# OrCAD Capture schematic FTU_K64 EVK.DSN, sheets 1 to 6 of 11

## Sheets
1 PAGE01 Diagram&Revision History: title: K64 FTU EVK; rev: X; company: Freescale Semiconductor; note: SCH-XXXXX PDF: SPF-XXXXX; note: 6501 William Cannon Drive West; note: Austin, TX 78735-8598
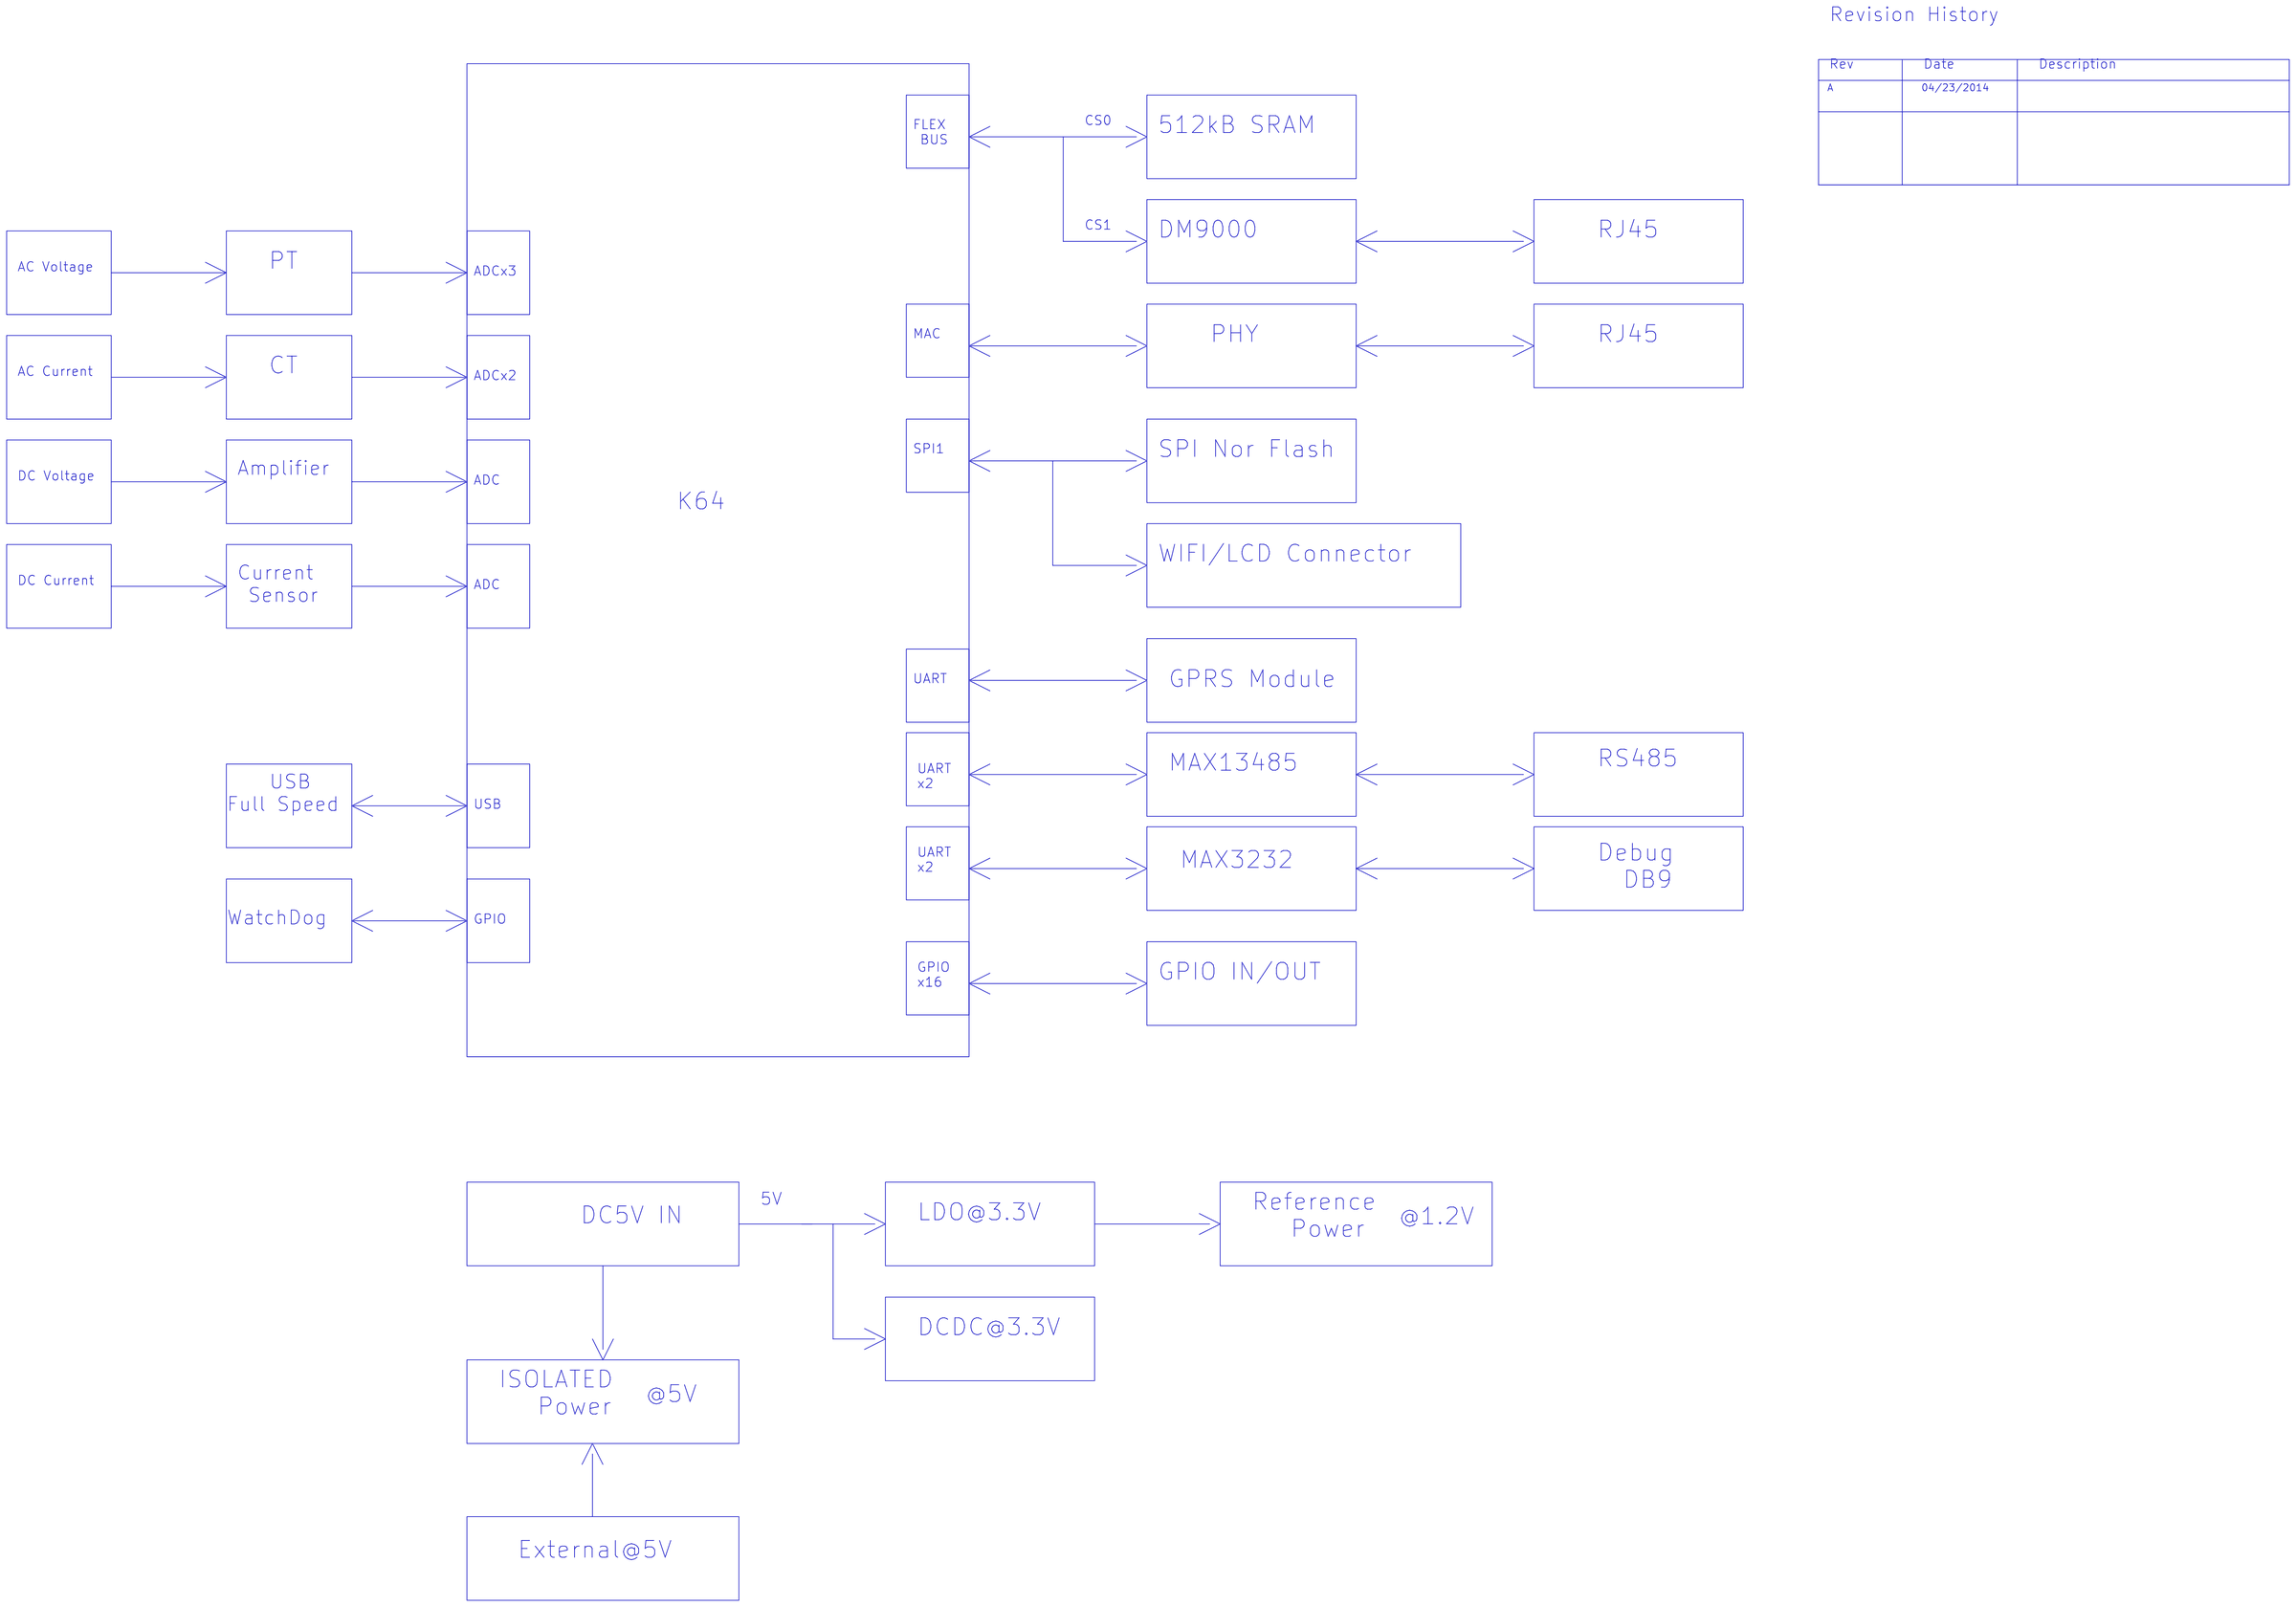
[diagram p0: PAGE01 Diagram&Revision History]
2 PAGE02 MCU: size A2
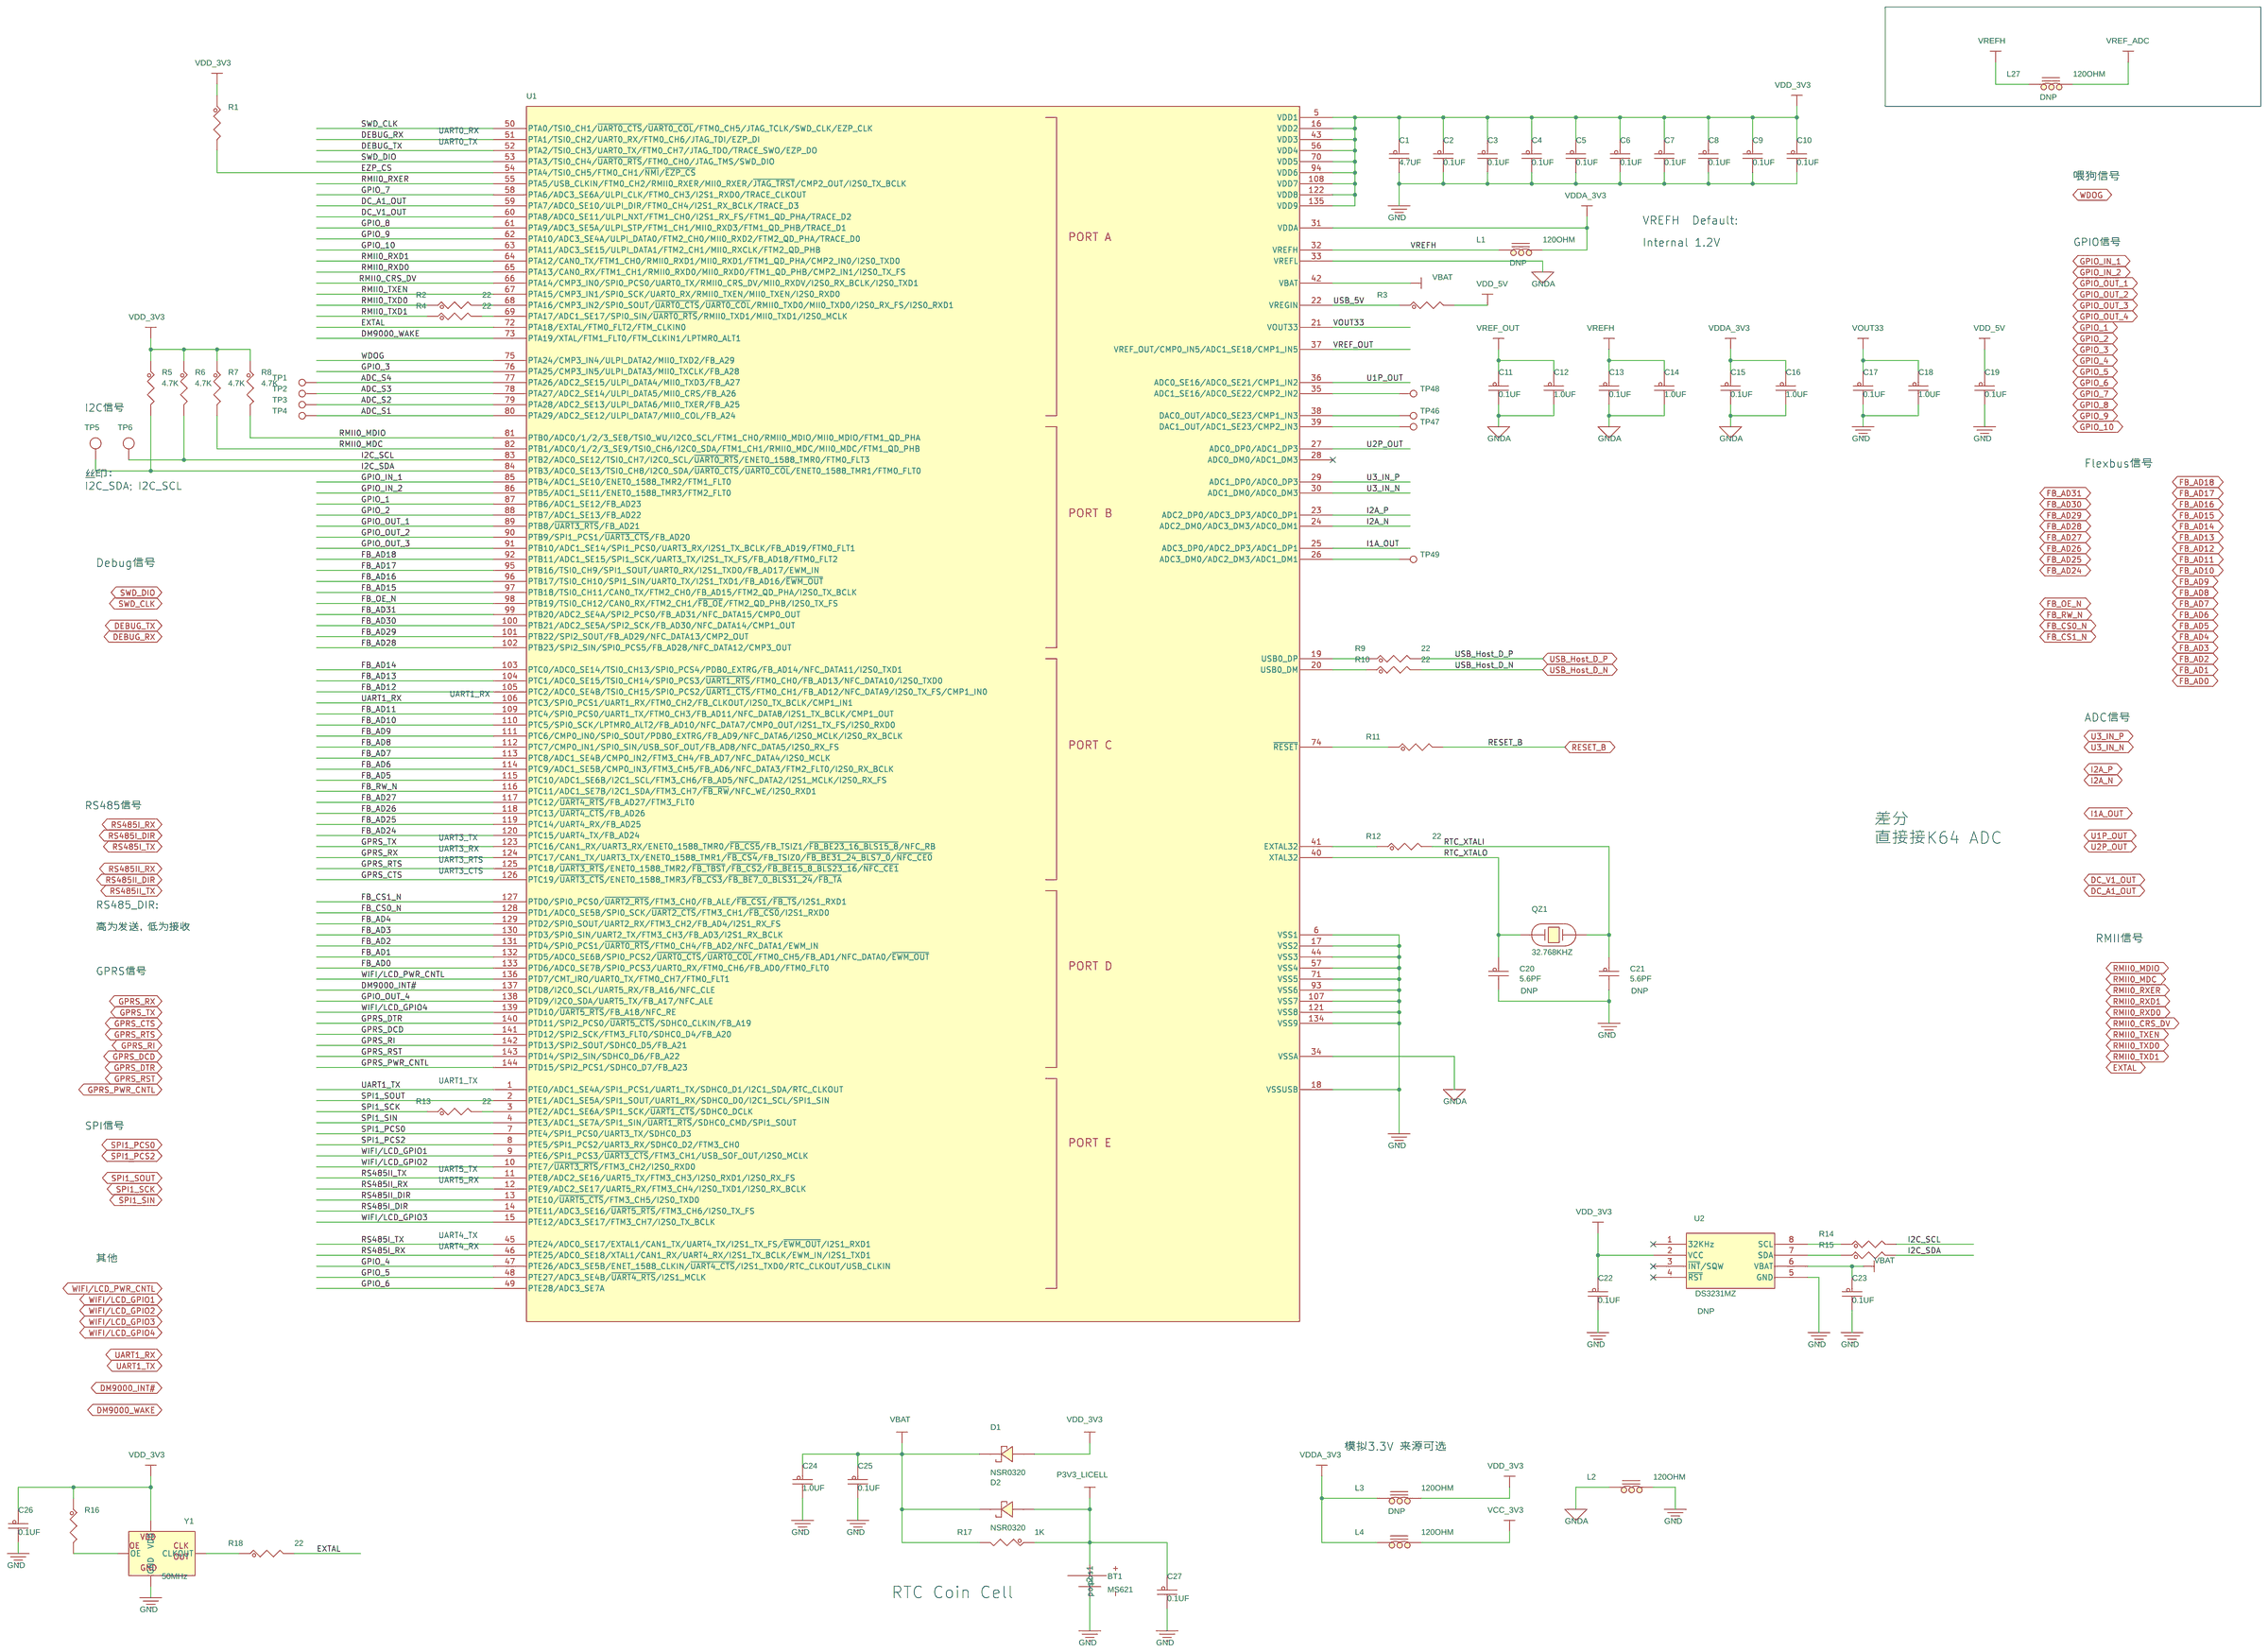
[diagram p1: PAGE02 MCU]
3 PAGE03 Memory: size A4
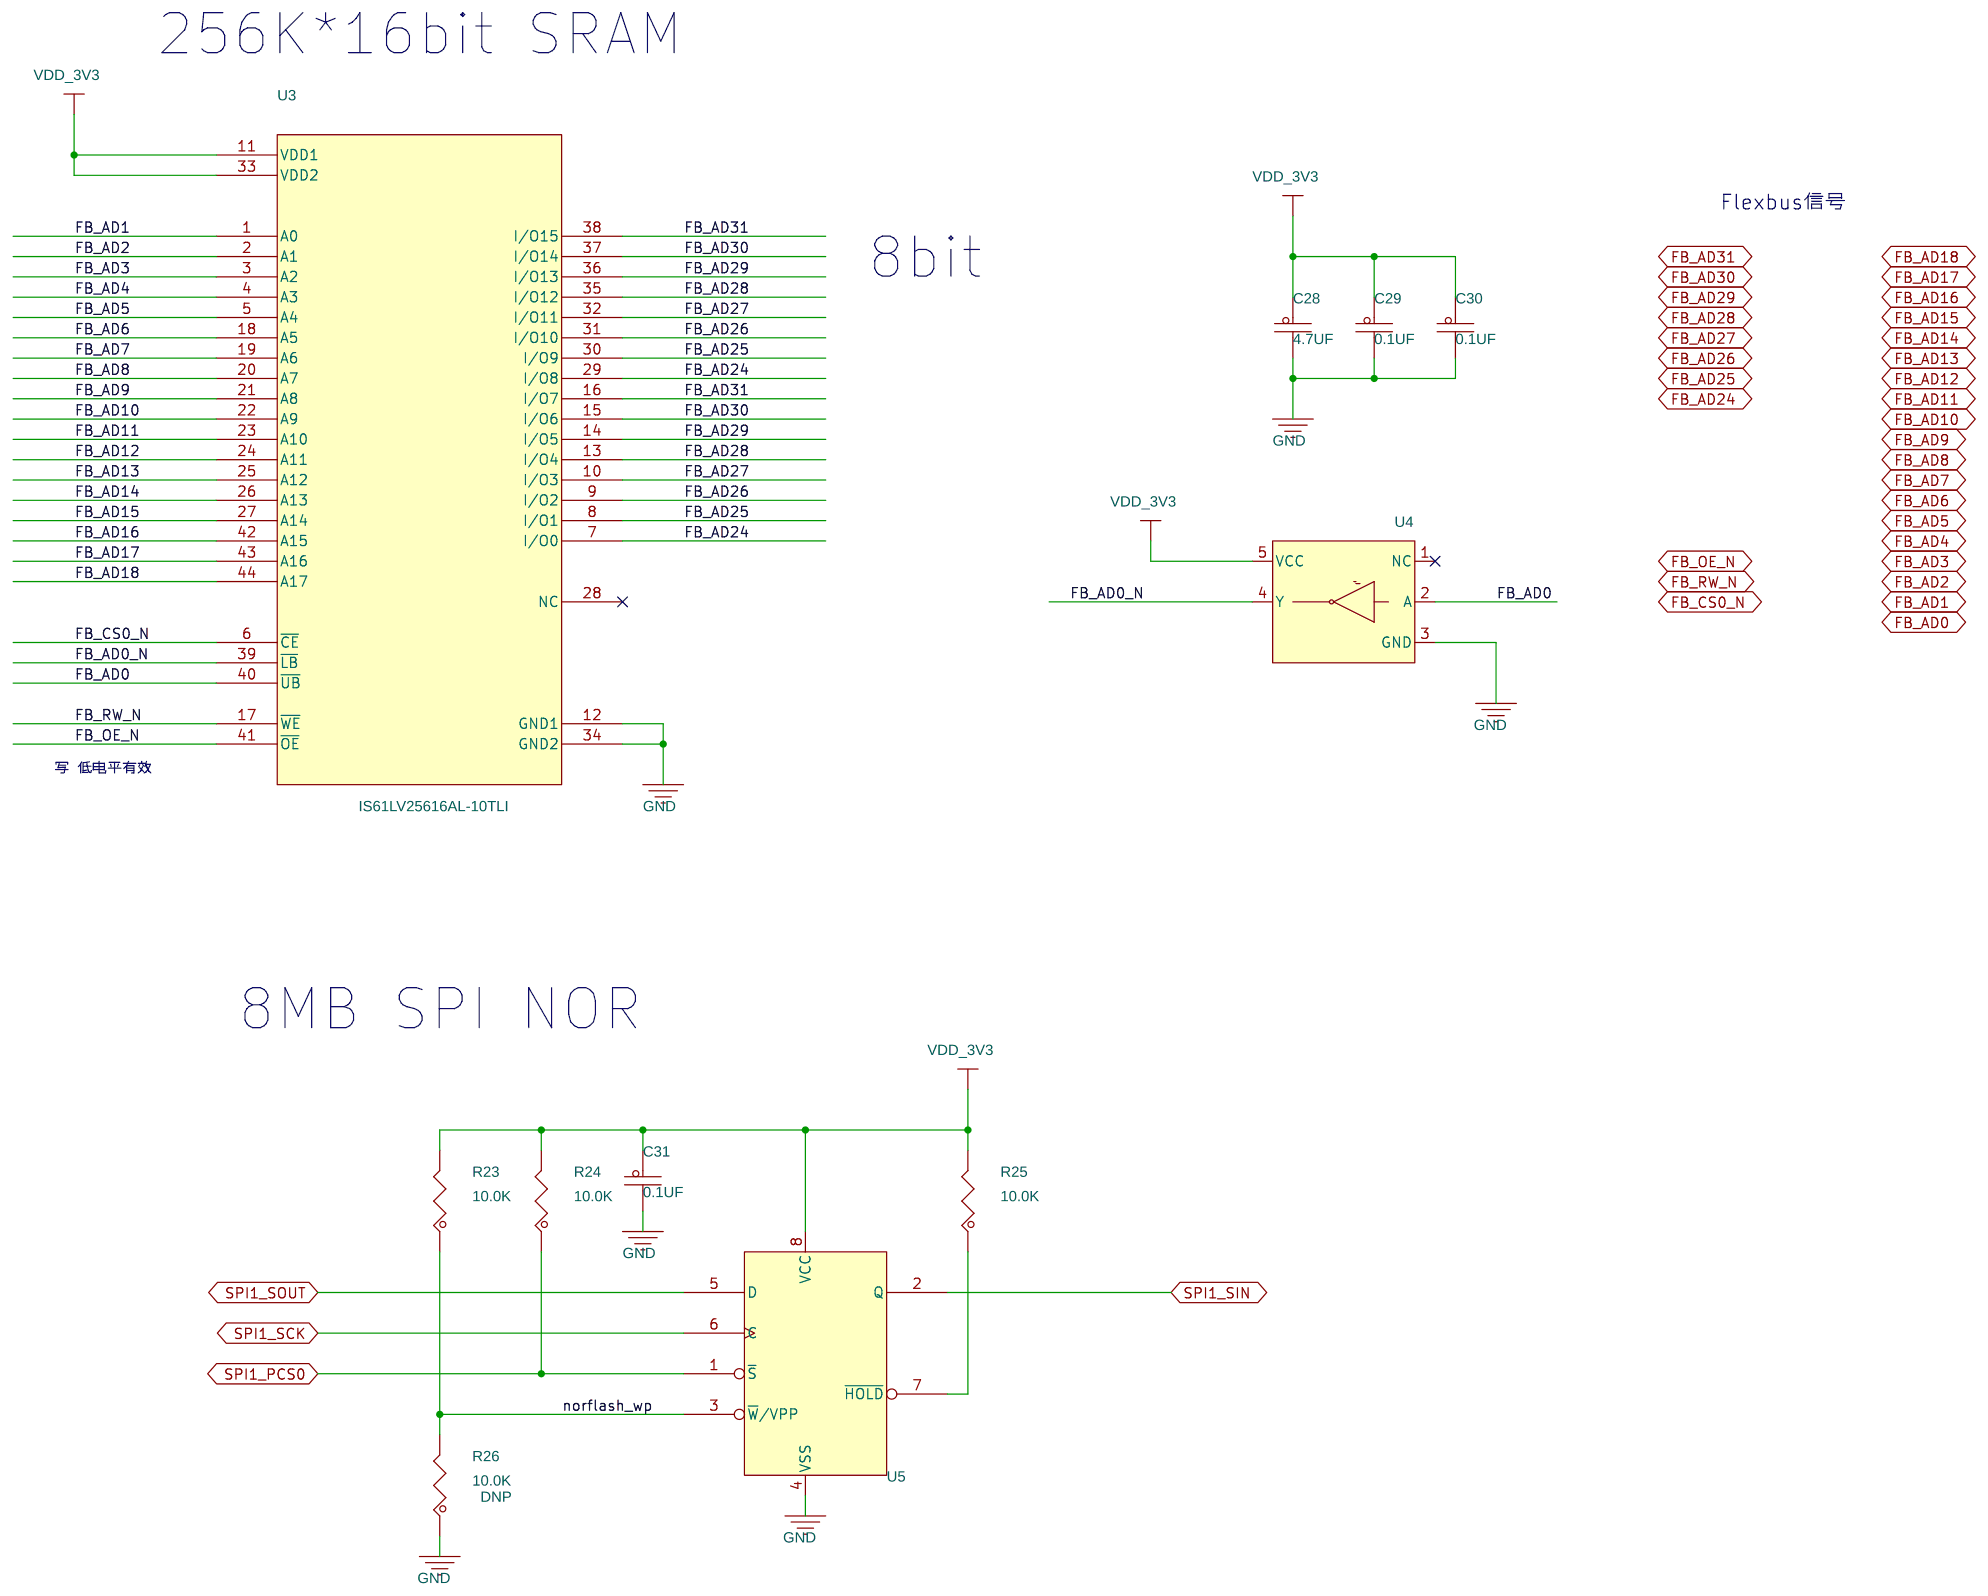
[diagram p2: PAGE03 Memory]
4 PAGE04 ADC: size C
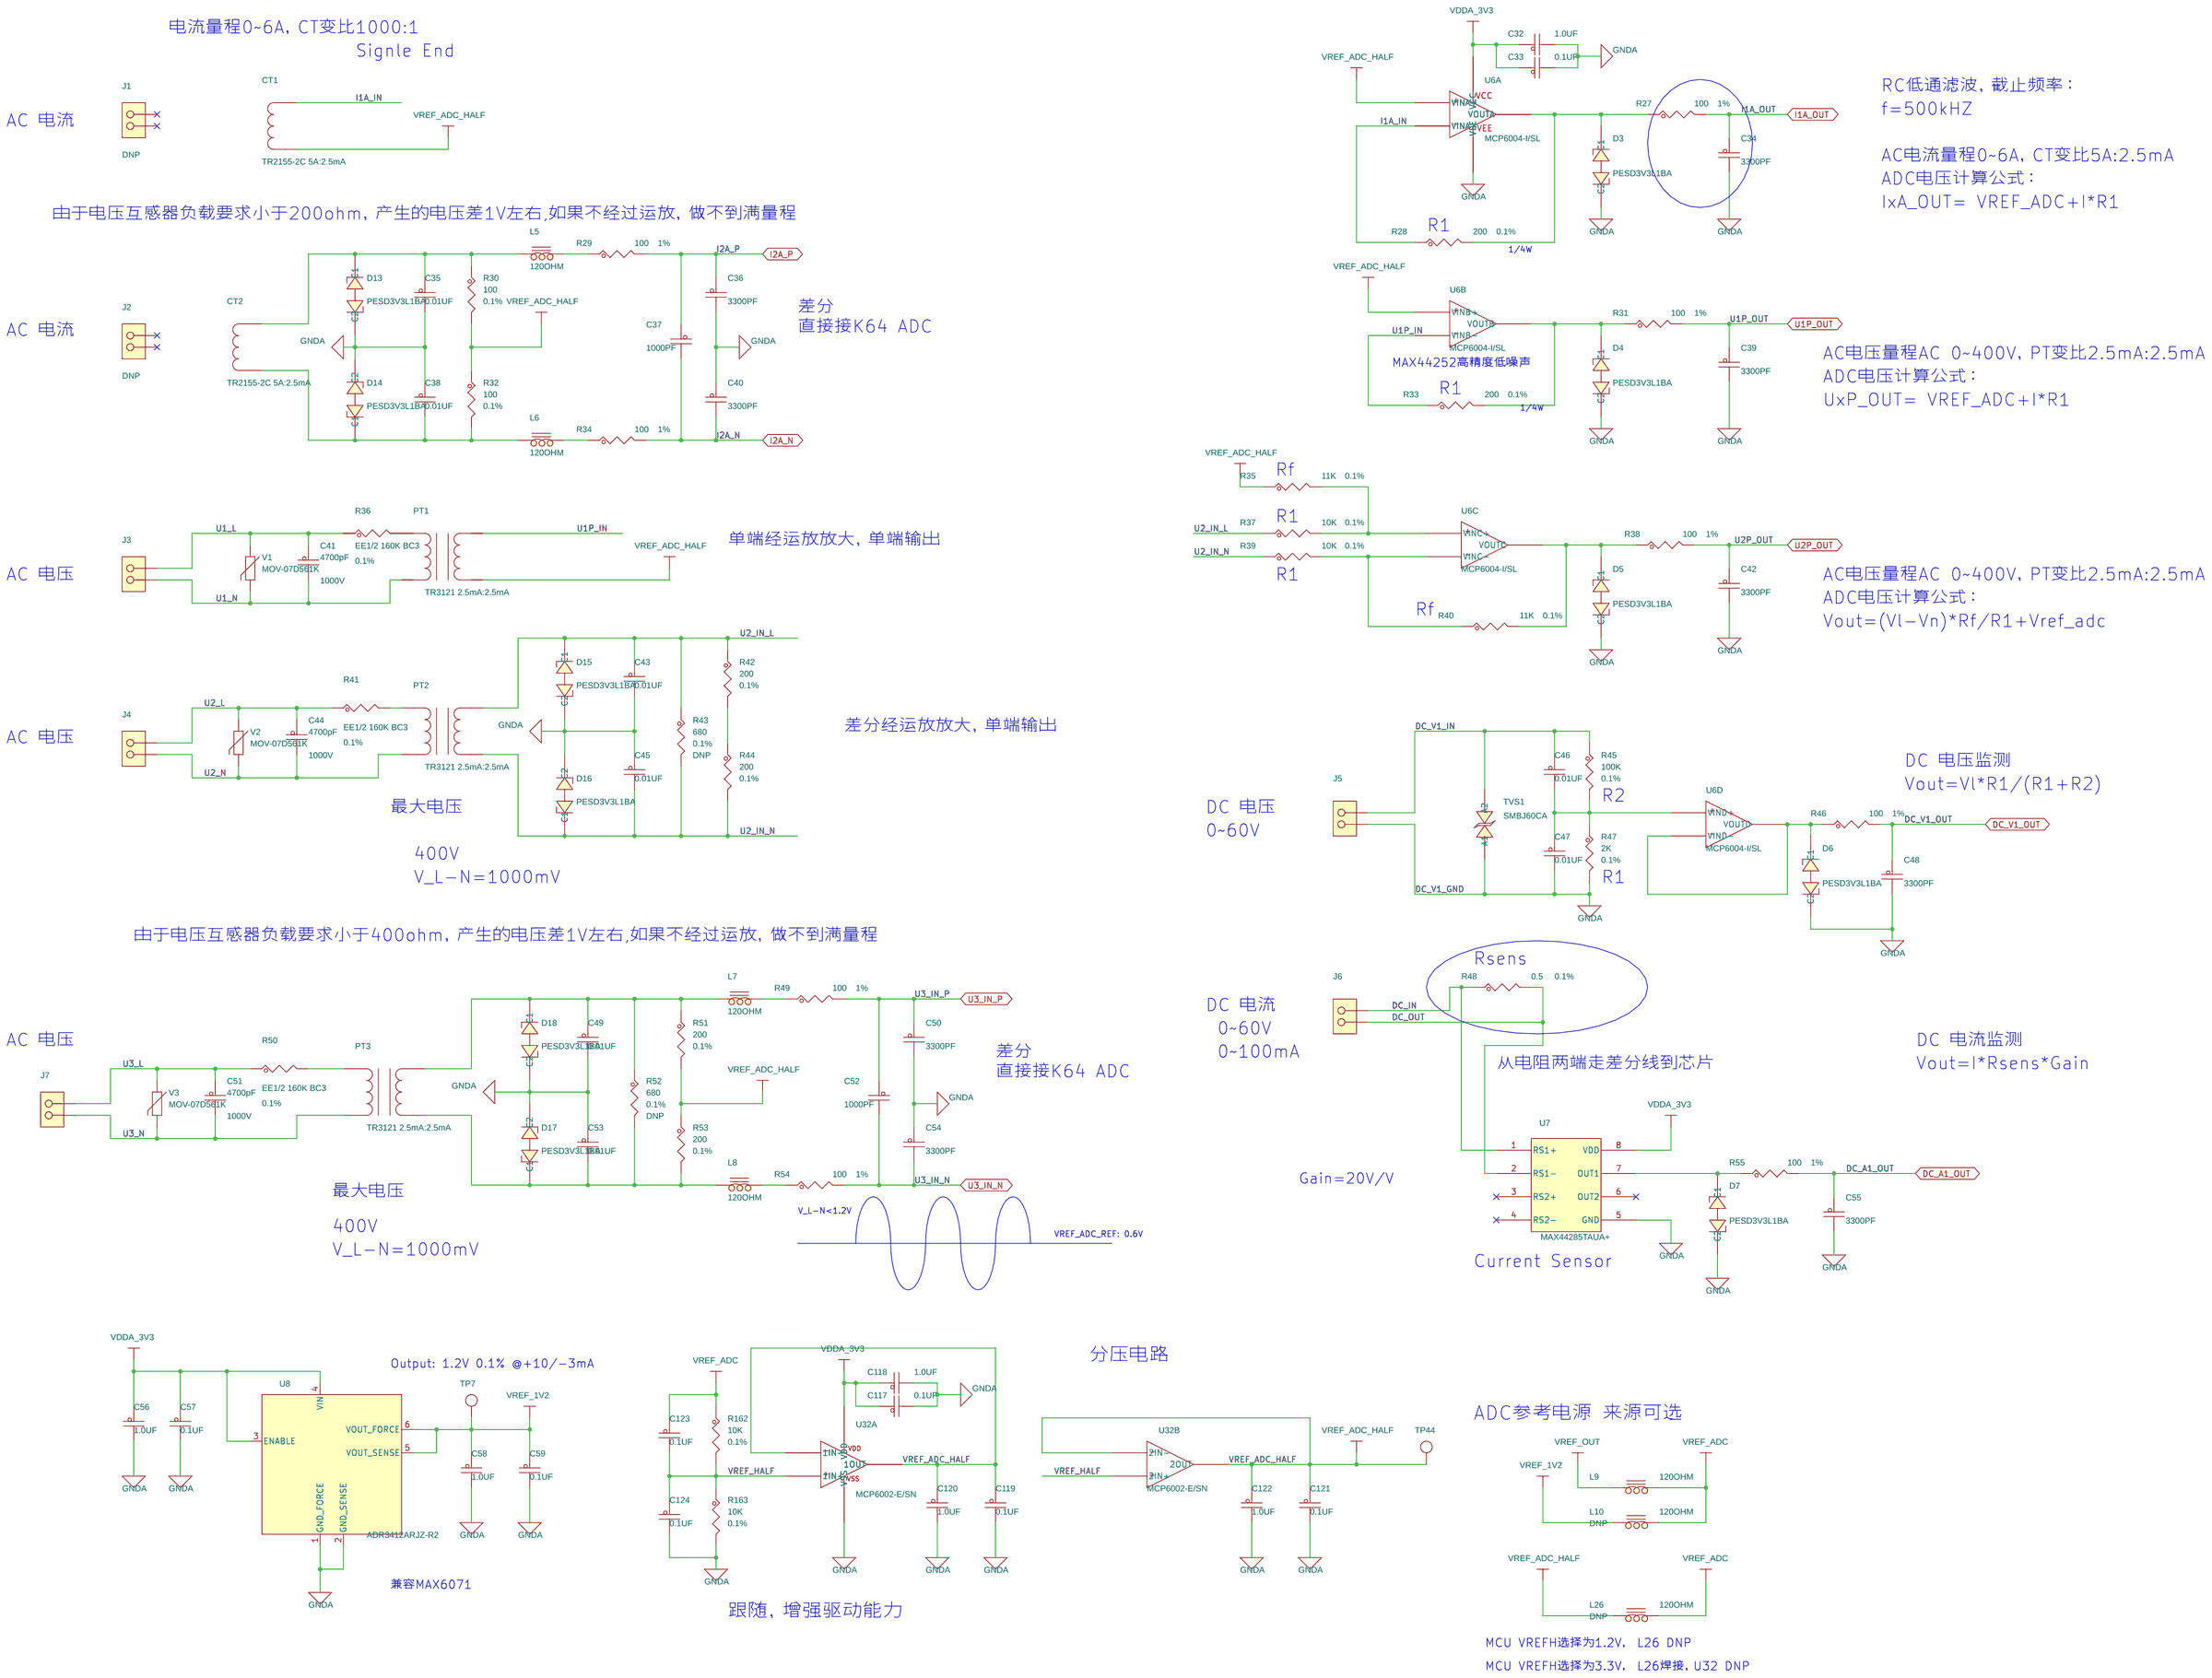
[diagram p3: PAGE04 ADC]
5 PAGE05 Ethernet: size A2
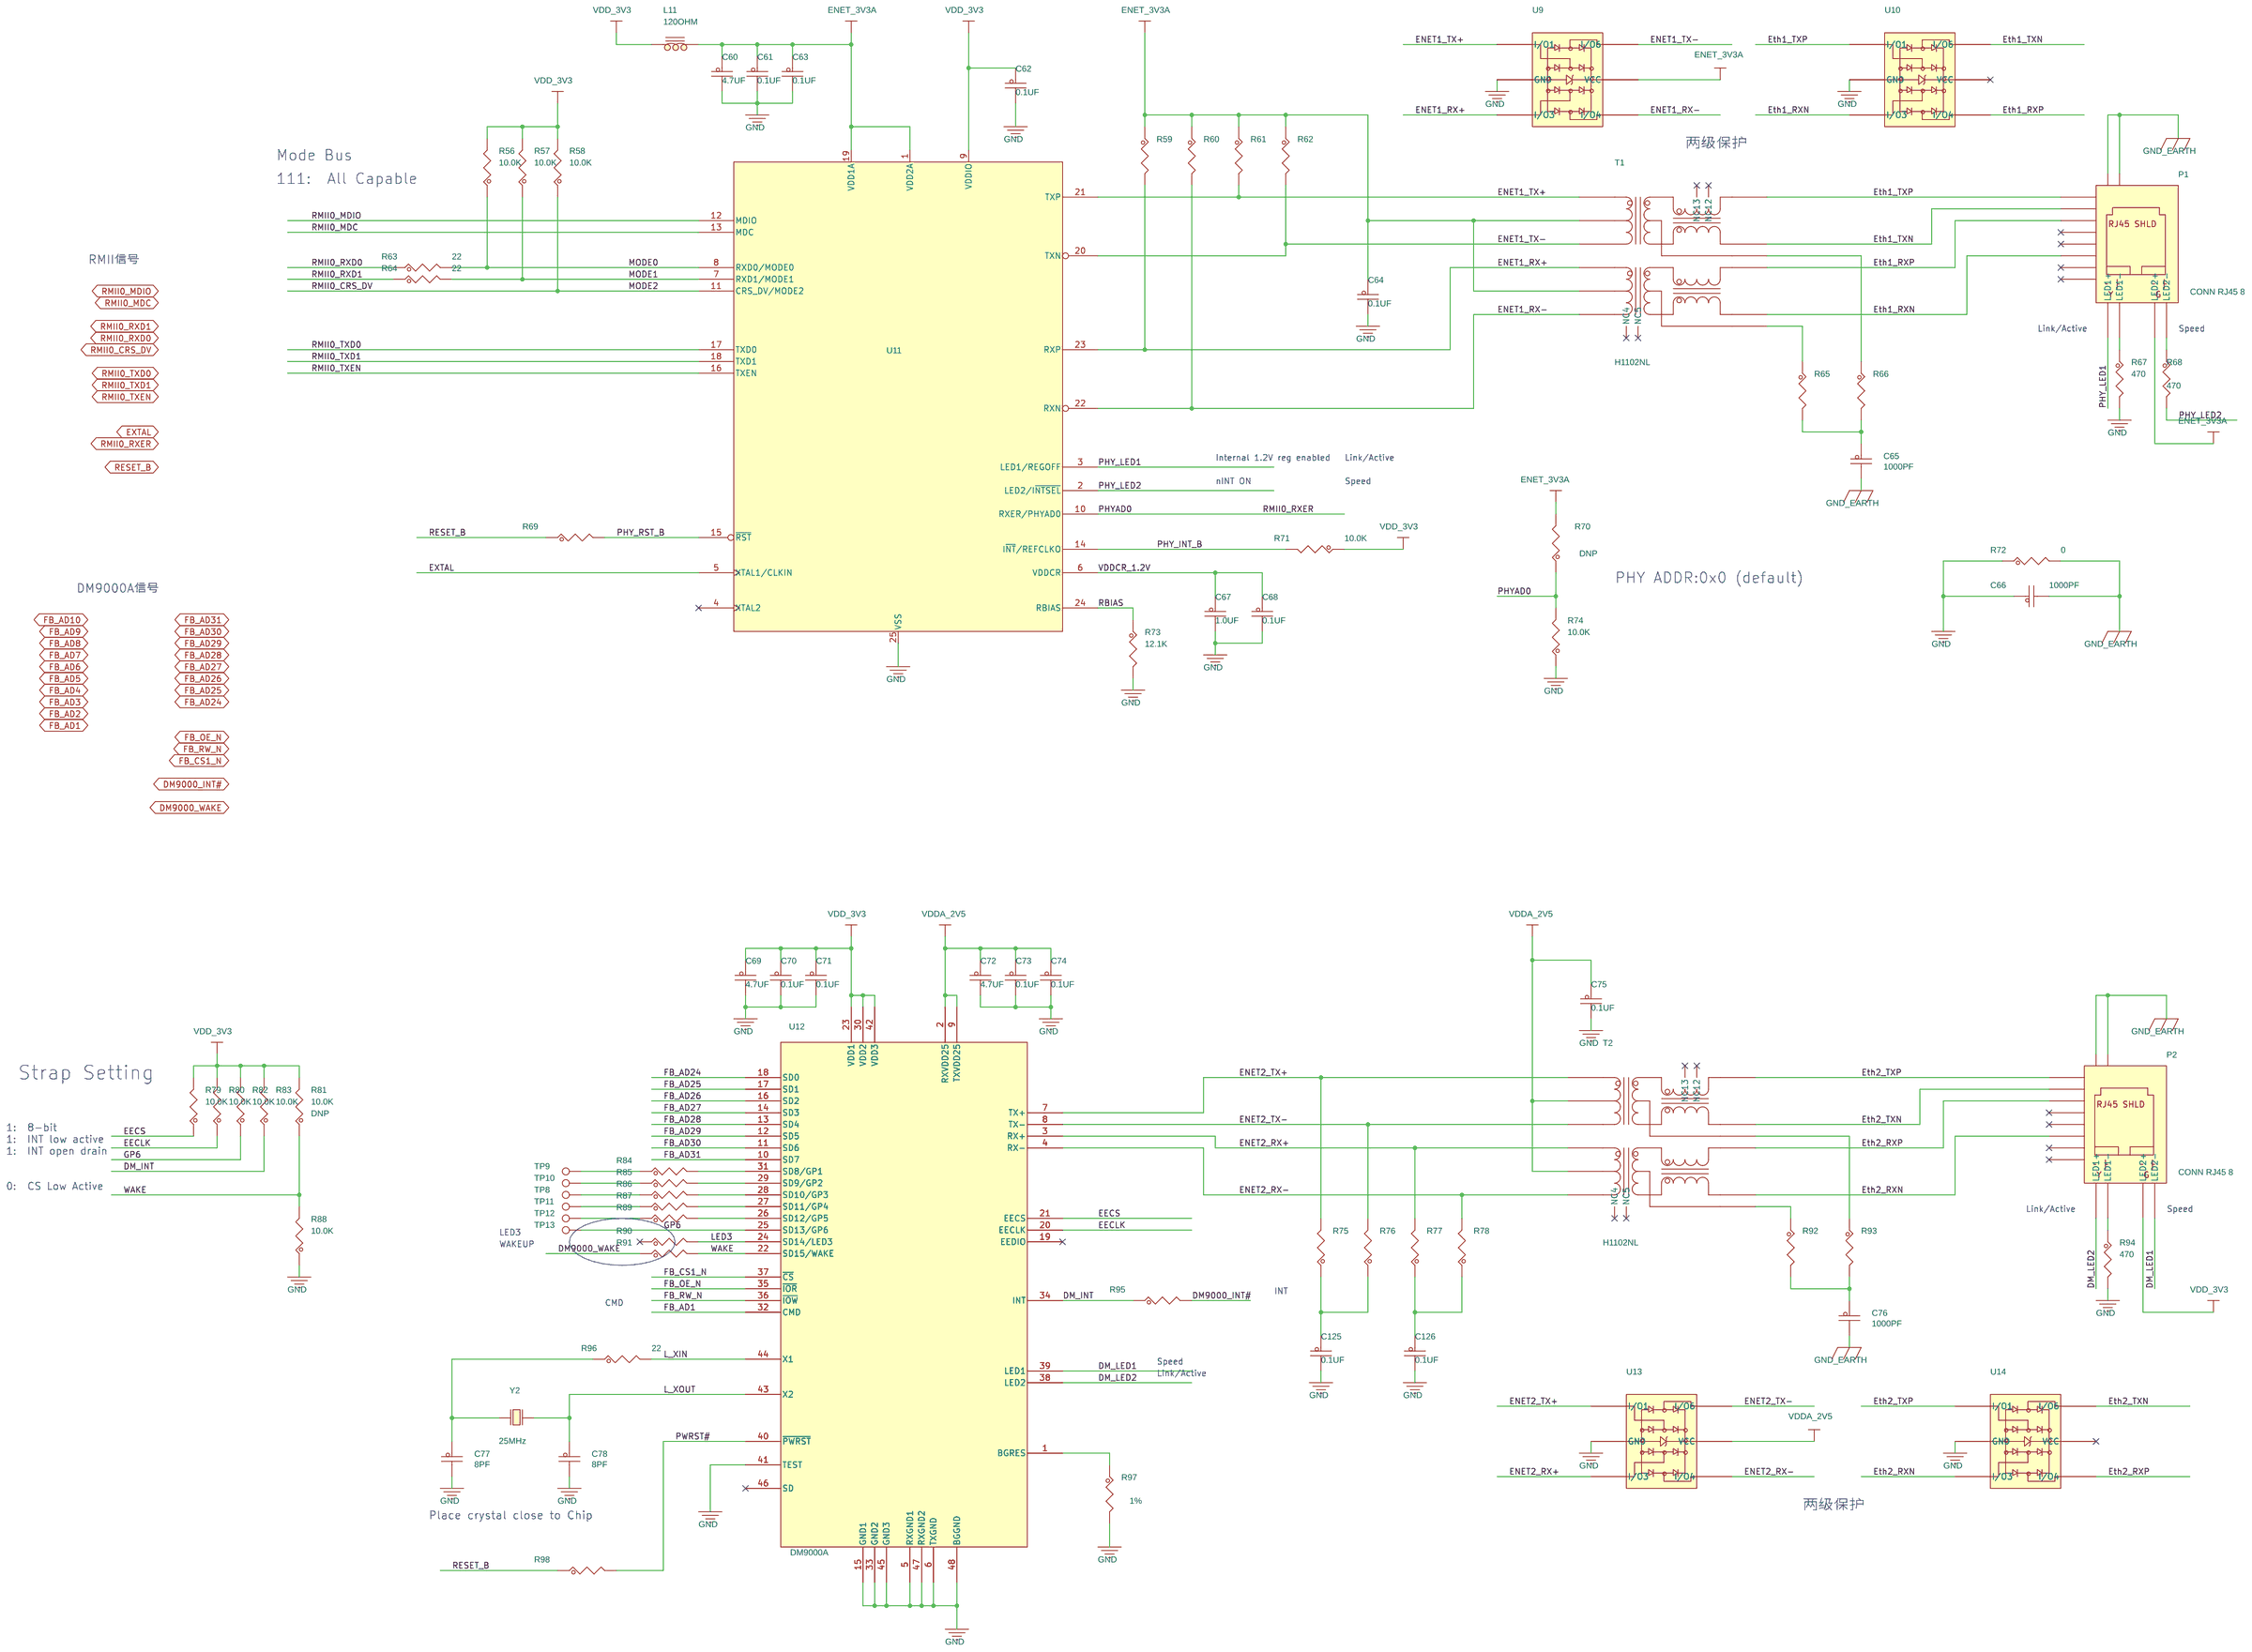
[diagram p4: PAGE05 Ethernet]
6 PAGE06 GPIO: size A4
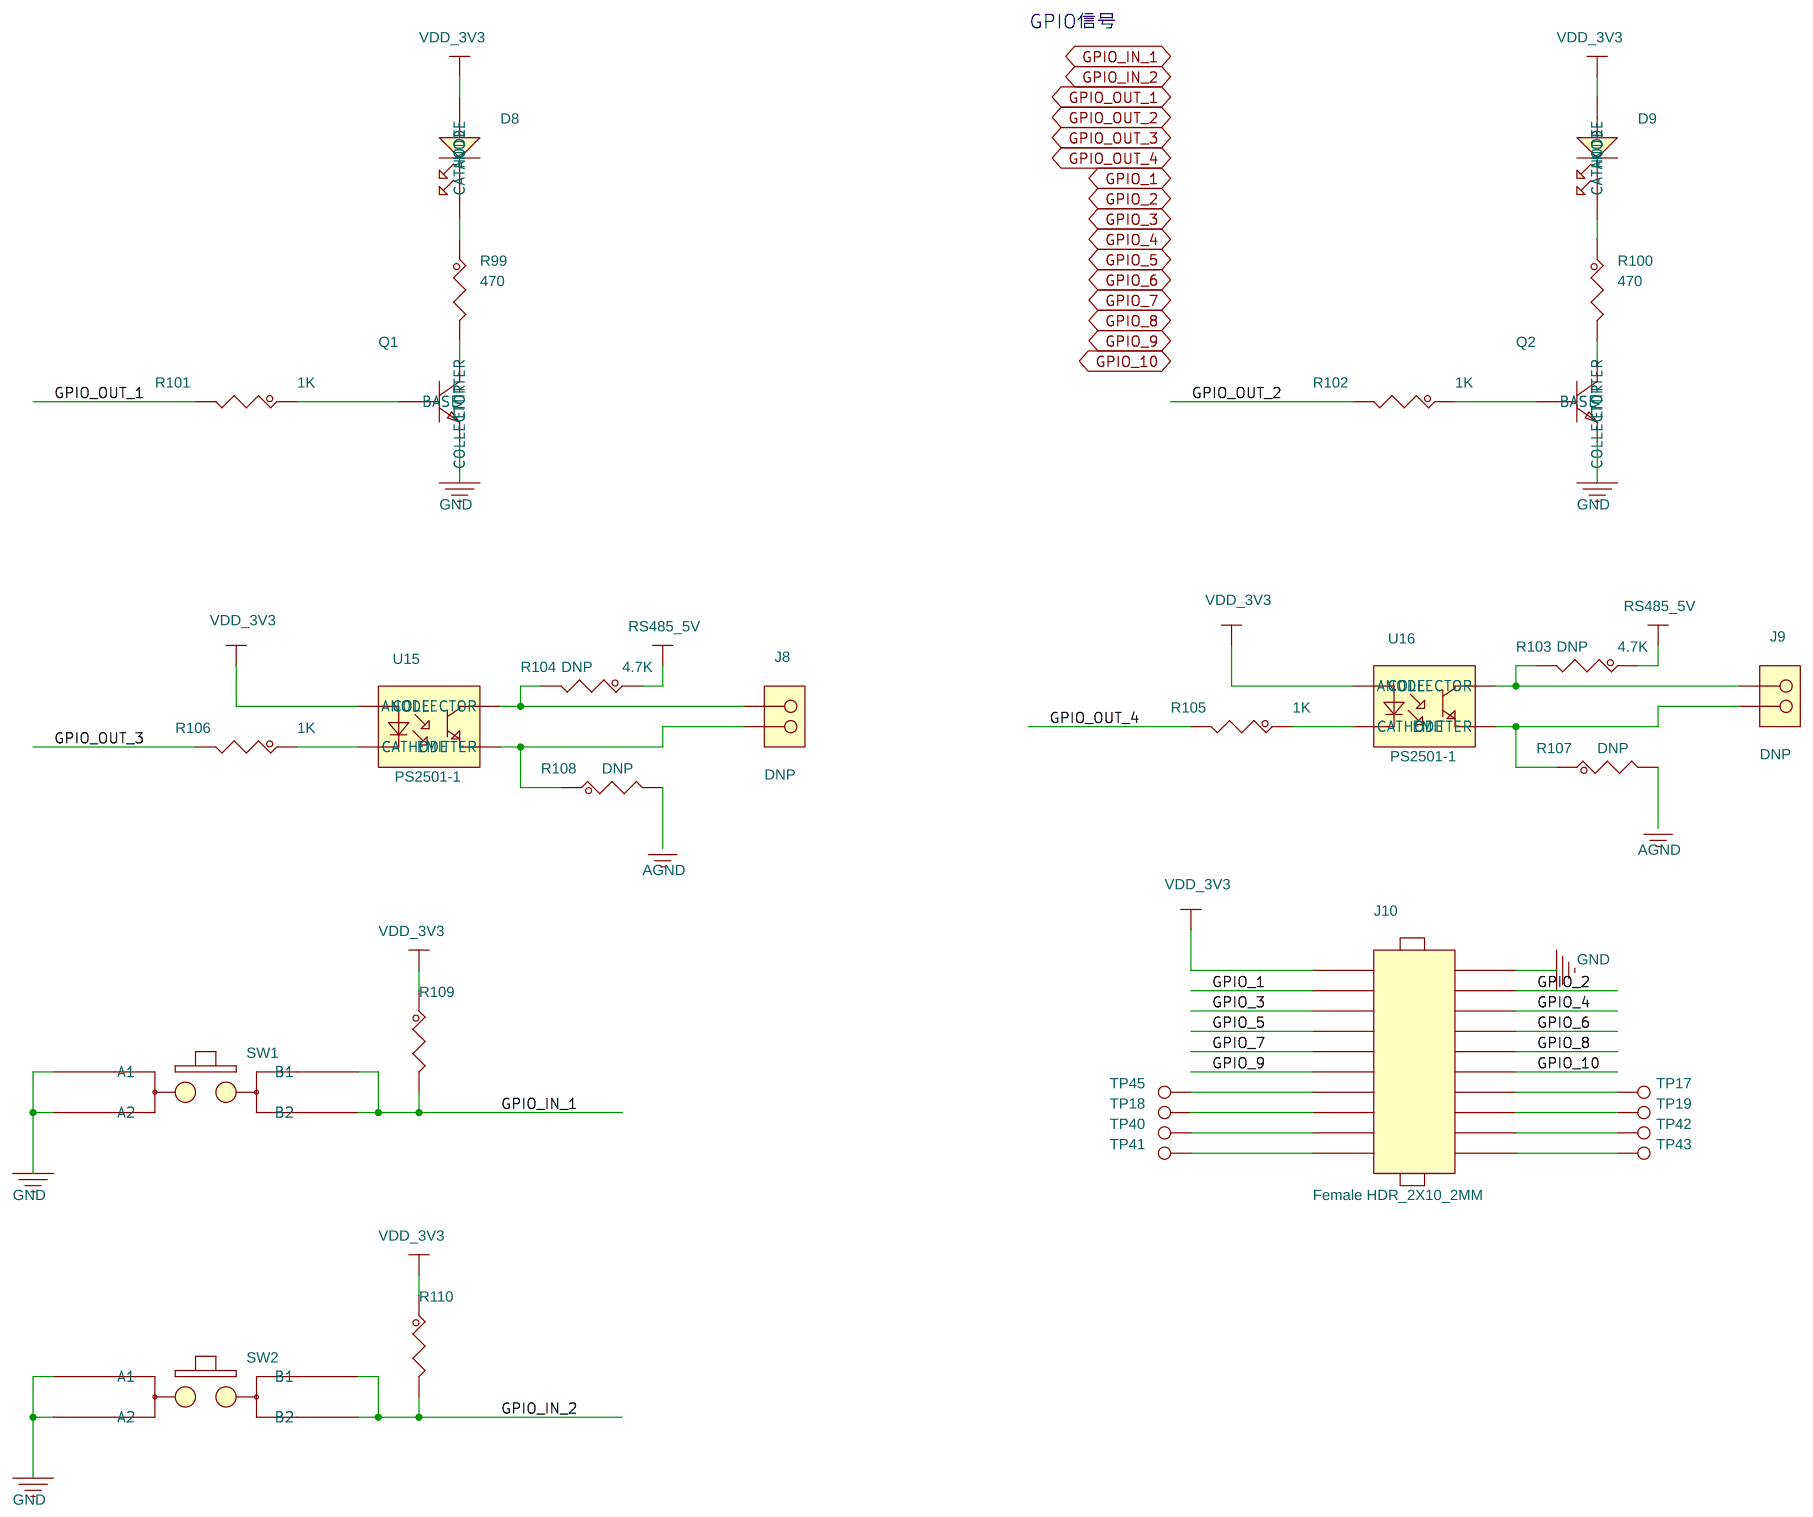
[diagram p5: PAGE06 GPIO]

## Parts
sheet PAGE02 MCU
BT1  MS621  [BAT_621]
C1  4.7UF  [CC0603]
C2  0.1UF  [CC0603]
C3  0.1UF  [CC0603]
C4  0.1UF  [CC0603]
C5  0.1UF  [CC0603]
C6  0.1UF  [CC0603]
C7  0.1UF  [CC0603]
C8  0.1UF  [CC0603]
C9  0.1UF  [CC0603]
C10  0.1UF  [CC0603]
C11  0.1UF  [CC0603]
C12  1.0UF  [CC0603]
C13  0.1UF  [CC0603]
C14  1.0UF  [CC0603]
C15  0.1UF  [CC0603]
C16  1.0UF  [CC0603]
C17  0.1UF  [CC0603]
C18  1.0UF  [CC0603]
C19  0.1UF  [CC0603]
C20  5.6PF  [CC0603]
C21  5.6PF  [CC0603]
C22  0.1UF  [CC0603]
C23  0.1UF  [CC0603]
C24  1.0UF  [CC0603]
C25  0.1UF  [CC0603]
C26  0.1UF  [CC0603]
C27  0.1UF  [CC0603]
D1  NSR0320  [SOD323]
D2  NSR0320  [SOD323]
L1  120OHM  [IND_0603]
L2  120OHM  [IND_0603]
L3  120OHM  [IND_0603]
L4  120OHM  [IND_0603]
L27  120OHM  [IND_0603]
QZ1  32.768KHZ  [XTAL2-3P2X1P5-SM]
R1  10.0K  [RC0603]
R2  22  [RC0603]
R3  0  [RC0603]
R4  22  [RC0603]
R5  4.7K  [RC0603]
R6  4.7K  [RC0603]
R7  4.7K  [RC0603]
R8  4.7K  [RC0603]
R9  22  [RC0603]
R10  22  [RC0603]
R11  0  [RC0603]
R12  22  [RC0603]
R13  22  [RC0603]
R14  0  [RC0603]
R15  0  [RC0603]
R16  10.0K  [RC0603]
R17  1K  [RC0603]
R18  22  [RC0603]
TP1  TEST POINT  [C035S]
TP2  TEST POINT  [C035S]
TP3  TEST POINT  [C035S]
TP4  TEST POINT  [C035S]
TP5  TPAD_040  [TPAD_040]
TP6  TPAD_040  [TPAD_040]
TP46  TEST POINT  [C035S]
TP47  TEST POINT  [C035S]
TP48  TEST POINT  [C035S]
TP49  TEST POINT  [C035S]
U1  MK64FN1M0VLQ12  [LQFP144_0P5_20X20MM]
U2  DS3231MZ  [so8_1p27_4x5]
Y1  50MHz  [osc4_5p15x3p35mm]
sheet PAGE03 Memory
C28  4.7UF  [CC0603]
C29  0.1UF  [CC0603]
C30  0.1UF  [CC0603]
C31  0.1UF  [CC0603]
R23  10.0K  [RC0603]
R24  10.0K  [RC0603]
R25  10.0K  [RC0603]
R26  10.0K  [RC0603]
U3  IS61LV25616AL-10TLI  [tsop44_t2]
U4  SN74LVC1G04  [SOT-23-5]
U5  W25Q64BVSSIG  [SO8WST]
sheet PAGE04 ADC
C32  1.0UF  [CC0603]
C33  0.1UF  [CC0603]
C34  3300PF  [CC0603]
C35  0.01UF  [CC0603]
C36  3300PF  [CC0603]
C37  1000PF  [CC0603]
C38  0.01UF  [CC0603]
C39  3300PF  [CC0603]
C40  3300PF  [CC0603]
C41  4700pF  [CC1210]
C42  3300PF  [CC0603]
C43  0.01UF  [CC0603]
C44  4700pF  [CC1210]
C45  0.01UF  [CC0603]
C46  0.01UF  [CC0603]
C47  0.01UF  [CC0603]
C48  3300PF  [CC0603]
C49  0.01UF  [CC0603]
C50  3300PF  [CC0603]
C51  4700pF  [CC1210]
C52  1000PF  [CC0603]
C53  0.01UF  [CC0603]
C54  3300PF  [CC0603]
C55  3300PF  [CC0603]
C56  1.0UF  [CC0603]
C57  0.1UF  [CC0603]
C58  1.0UF  [CC0603]
C59  0.1UF  [CC0603]
C117  0.1UF  [CC0603]
C118  1.0UF  [CC0603]
C119  0.1UF  [CC0603]
C120  1.0UF  [CC0603]
C121  0.1UF  [CC0603]
C122  1.0UF  [CC0603]
C123  0.1UF  [CC0603]
C124  0.1UF  [CC0603]
CT1  TR2155-2C 5A:2.5mA  [CT_2A]
CT2  TR2155-2C 5A:2.5mA  [CT_2A]
D3  PESD3V3L1BA  [sod323]
D4  PESD3V3L1BA  [sod323]
D5  PESD3V3L1BA  [sod323]
D6  PESD3V3L1BA  [sod323]
D7  PESD3V3L1BA  [sod323]
D13  PESD3V3L1BA  [sod323]
D14  PESD3V3L1BA  [sod323]
D15  PESD3V3L1BA  [sod323]
D16  PESD3V3L1BA  [sod323]
D17  PESD3V3L1BA  [sod323]
D18  PESD3V3L1BA  [sod323]
J1  HDR 1X2  [hdr102]
J2  HDR 1X2  [hdr102]
J3  HDR 1X2  [hdr102]
J4  HDR 1X2  [hdr102]
J5  HDR 1X2  [hdr102]
J6  HDR 1X2  [hdr102]
J7  HDR 1X2  [hdr102]
L5  120OHM  [IND_0603]
L6  120OHM  [IND_0603]
L7  120OHM  [IND_0603]
L8  120OHM  [IND_0603]
L9  120OHM  [IND_0603]
L10  120OHM  [IND_0603]
L26  120OHM  [IND_0603]
PT1  TR3121 2.5mA:2.5mA  [PT_4P]
PT2  TR3121 2.5mA:2.5mA  [PT_4P]
PT3  TR3121 2.5mA:2.5mA  [PT_4P]
R27  100  [RC0603]
R28  200  [RC_MELF_0204]
R29  100  [RC0603]
R30  100  [RC_MELF_0204]
R31  100  [RC0603]
R32  100  [RC_MELF_0204]
R33  200  [RC_MELF_0204]
R34  100  [RC0603]
R35  11K  [RC_MELF_0204]
R36  EE1/2 160K BC3  [RES_TH]
R37  10K  [RC_MELF_0204]
R38  100  [RC0603]
R39  10K  [RC_MELF_0204]
R40  11K  [RC_MELF_0204]
R41  EE1/2 160K BC3  [RES_TH]
R42  200  [RC_MELF_0204]
R43  680  [RC_MELF_0204]
R44  200  [RC_MELF_0204]
R45  100K  [RC_MELF_0204]
R46  100  [RC0603]
R47  2K  [RC_MELF_0204]
R48  0.5  [RC2010]
R49  100  [RC0603]
R50  EE1/2 160K BC3  [RES_TH]
R51  200  [RC_MELF_0204]
R52  680  [RC_MELF_0204]
R53  200  [RC_MELF_0204]
R54  100  [RC0603]
R55  100  [RC0603]
R162  10K  [RC_MELF_0204]
R163  10K  [RC_MELF_0204]
TP7  TPAD_040  [TPAD_040]
TP44  TPAD_040  [TPAD_040]
TVS1  SMBJ60CA  [do-214aa_bidir]
U6  MCP6004-I/SL  [soic14_1p27_4x8]  (sections A,B,C,D)
U7  MAX44285TAUA+  [MSOP08_0P65_3P2X3P2]
U8  ADR3412ARJZ-R2  [SOT23-6]
U32  MCP6002-E/SN  [SO8_1P27_4X5]  (sections A,B)
V1  MOV-07D561K  [varistor_5_9x5p8_th]
V2  MOV-07D561K  [varistor_5_9x5p8_th]
V3  MOV-07D561K  [varistor_5_9x5p8_th]
sheet PAGE05 Ethernet
C60  4.7UF  [CC0603]
C61  0.1UF  [CC0603]
C62  0.1UF  [CC0603]
C63  0.1UF  [CC0603]
C64  0.1UF  [CC0603]
C65  1000PF  [CC1206]
C66  1000PF  [CC1206]
C67  1.0UF  [CC0603]
C68  0.1UF  [CC0603]
C69  4.7UF  [CC0603]
C70  0.1UF  [CC0603]
C71  0.1UF  [CC0603]
C72  4.7UF  [CC0603]
C73  0.1UF  [CC0603]
C74  0.1UF  [CC0603]
C75  0.1UF  [CC0603]
C76  1000PF  [CC1206]
C77  8PF  [CC0603]
C78  8PF  [CC0603]
C125  0.1UF  [CC0603]
C126  0.1UF  [CC0603]
L11  120OHM  [IND_0603]
P1  CONN RJ45 8  [con8_rj45_led_jack]
P2  CONN RJ45 8  [con8_rj45_led_jack]
R56  10.0K  [RC0603]
R57  10.0K  [RC0603]
R58  10.0K  [RC0603]
R59  49.9  [RC0603]
R60  49.9  [RC0603]
R61  49.9  [RC0603]
R62  49.9  [RC0603]
R63  22  [RC0603]
R64  22  [RC0603]
R65  75.0  [RC0603]
R66  75.0  [RC0603]
R67  470  [RC0603]
R68  470  [RC0603]
R69  0  [RC0603]
R70  0  [RC0603]
R71  10.0K  [RC0603]
R72  0  [RC0805]
R73  12.1K  [RC0603]
R74  10.0K  [RC0603]
R75  49.9  [RC0603]
R76  49.9  [RC0603]
R77  49.9  [RC0603]
R78  49.9  [RC0603]
R79  10.0K  [RC0603]
R80  10.0K  [RC0603]
R81  10.0K  [RC0603]
R82  10.0K  [RC0603]
R83  10.0K  [RC0603]
R84  0  [RC0603]
R85  0  [RC0603]
R86  0  [RC0603]
R87  0  [RC0603]
R88  10.0K  [RC0603]
R89  0  [RC0603]
R90  0  [RC0603]
R91  0  [RC0603]
R92  75.0  [RC0603]
R93  75.0  [RC0603]
R94  470  [RC0603]
R95  0  [RC0603]
R96  22  [RC0603]
R97  6.80K  [RC0603]
R98  0  [RC0603]
T1  H1102NL  [H1102_XFMR16_SM]
T2  H1102NL  [H1102_XFMR16_SM]
TP8  TEST POINT  [C035S]
TP9  TEST POINT  [C035S]
TP10  TEST POINT  [C035S]
TP11  TEST POINT  [C035S]
TP12  TEST POINT  [C035S]
TP13  TEST POINT  [C035S]
U9  SRV05-4  [SOT23-6]
U10  SRV05-4  [SOT23-6]
U11  LAN8720A  [qfn24_4X4mm_slug]
U12  DM9000A  [LQFP48]
U13  SRV05-4  [SOT23-6]
U14  SRV05-4  [SOT23-6]
Y2  25MHz  [XTAL2_4_5P2X3P4]
sheet PAGE06 GPIO
D8  RED  [LED_0603]
D9  RED  [LED_0603]
J8  HDR 1X2  [hdr102]
J9  HDR 1X2  [hdr102]
J10  Female HDR_2X10_2MM  [HDR210_2MM]
Q1  MMBT3904LT1G  [SOT-23]
Q2  MMBT3904LT1G  [SOT-23]
R99  470  [RC0603]
R100  470  [RC0603]
R101  1K  [RC0603]
R102  1K  [RC0603]
R103  4.7K  [RC0603]
R104  4.7K  [RC0603]
R105  1K  [RC0603]
R106  1K  [RC0603]
R107  0  [RC0603]
R108  0  [RC0603]
R109  10.0K  [RC0603]
R110  10.0K  [RC0603]
SW1  SPST PB  [SW4_PB_ESW_SM_P177]
SW2  SPST PB  [SW4_PB_ESW_SM_P177]
TP17  TEST POINT  [C035S]
TP18  TEST POINT  [C035S]
TP19  TEST POINT  [C035S]
TP40  TEST POINT  [C035S]
TP41  TEST POINT  [C035S]
TP42  TEST POINT  [C035S]
TP43  TEST POINT  [C035S]
TP45  TEST POINT  [C035S]
U15  PS2501-1  [4dip300]
U16  PS2501-1  [4dip300]

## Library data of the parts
BT1 = BATTERY_SKT_1: BATTERY RETAINER COIN CELL 4.8MM SMT; AGILE_PN: 801-76071; CAD_APPROVED: Yes; HEIGHT: 1.7MM; MFG_NAME01: KEYSTONE ELECTRONICS; MFG_PN01: 2994TR; ROHS: Yes
C1 C28 C60 C69 C72 = CAP_NP: CAP CER 4.7UF 6.3V 10% X5R 0603; AGILE_PN: 150-75487; CAD_APPROVED: Yes; FPLIST: CC0603_OV,CC0603,CC0603_CC; HEIGHT: 1.016MM; MFG_NAME01: VENKEL COMPANY; MFG_PN01: C0603X5R6R3-475KNP; PRIORITY_PN: 021-00280; ROHS: Yes; ROOM: RMII_PHY; Tolerance: 10%
C2-C11 C13 C15 C17 C19 C22 C23 C25-C27 C29-C31 C33 C57 C59 C61-C64 C68 C70 C71 C73-C75 C117 C119 C121 C123-C126 = CAP_NP: CAP CER 0.10UF 25V 10% X7R 0603; AGILE_PN: 150-75016; CAD_APPROVED: Yes; FPLIST: CC0603_OV,CC0603,0603_CC; HEIGHT: 0.97 MM; MFG_NAME01: KEMET; MFG_PN01: C0603C104K3RAC; ROHS: Yes; Tolerance: 10%; VOLTAGE: 25V
C12 C14 C16 C18 C24 C32 C56 C58 C67 C118 C120 C122 = CAP_NP: CAP CER 1.0UF 16V 10% X5R 0603; AGILE_PN: 150-30124; CAD_APPROVED: Yes; FPLIST: CC0603_OV,CC0603,0603_CC; HEIGHT: 0.90MM; MFG_NAME01: TDK; MFG_PN01: C1608X5R1C105K; ROHS: Yes; Tolerance: 10%; VOLTAGE: 16V
C20 C21 = CAP_NP: CAP CER 18PF 50V 5% C0G 0603; AGILE_PN: 150-75116; ASSY_OPT: DNP; CAD_APPROVED: Yes; FPLIST: CC0603_OV,CC0603,0603_CC; HEIGHT: 0.90MM; MFG_NAME01: YAGEO AMERICA; MFG_PN01: CC0603JRNPO9BN180; ROHS: Yes; Tolerance: 5%; VOLTAGE: 50V
D1 D2 = DIODE_SCHTKY: DIODE SCH PWR RECT LOW VF 1A 20V SOD323; AGILE_PN: 480-77923; CAD_APPROVED: Yes; HEIGHT: 1.1MM; MFG_NAME01: ON Semiconductor; MFG_PN01: NSR0320MW2T1G; ROHS: Yes
L1 L3 L10 L26 L27 = BEAD_0: IND FER BEAD 120OHM@100MHZ 2A 25% 0603; AGILE_PN: 180-30008; ASSY_OPT: DNP; CAD_APPROVED: Yes; FPLIST: IND_0603,0603_CC; HEIGHT: 0.95MM; MFG_NAME01: MURATA; MFG_PN01: BLM18PG121SH1; PART_TYPE: FERRITE; PRIORITY_PN: 024-00067; ROHS: Yes; ROOM: RMII_PHY; Tolerance: 25%
L2 L4-L9 L11 = BEAD_0: IND FER BEAD 120OHM@100MHZ 2A 25% 0603; AGILE_PN: 180-30008; CAD_APPROVED: Yes; FPLIST: IND_0603,0603_CC; HEIGHT: 0.95MM; MFG_NAME01: MURATA; MFG_PN01: BLM18PG121SH1; PART_TYPE: FERRITE; PRIORITY_PN: 024-00067; ROHS: Yes; ROOM: RMII_PHY; Tolerance: 25%
QZ1 = XTAL: XTAL 32.768KHZ 12.5PF 20PPM 3.2X1.5MM SMT; AGILE_PN: 230-77653; CAD_APPROVED: Yes; HEIGHT: 0.9MM; MFG_NAME01: Abracon Corporation; MFG_PN01: ABS07-32.768KHZ-T; ROHS: Yes
R1 R16 R23-R25 R56-R58 R71 R74 R79 R80 R82 R83 R88 R109 R110 = RES: RES MF 10.0K 1/10W 1% 0603; AGILE_PN: 470-75422; CAD_APPROVED: Yes; FPLIST: RC0603_OV,RC0603,0603_CC; MFG_NAME01: KOA SPEER; MFG_PN01: RK73H1JTTD1002F; ROHS: Yes; Tolerance: 5%
R2 R4 R9 R10 R12 R13 R18 R63 R64 R96 = RES: RES MF 22 OHM 1/10W 5% 0603; AGILE_PN: 470-75398; CAD_APPROVED: Yes; FPLIST: RC0603_OV,RC0603,0603_CC; MFG_NAME01: KOA SPEER; MFG_PN01: RK73B1JTTD220J; ROHS: Yes; Tolerance: 5%
R3 R11 R14 R15 R69 R84-R87 R89-R91 R95 R98 = RES: RES MF ZERO OHM 1/10W -- 0603; AGILE_PN: 470-75407; CAD_APPROVED: Yes; FPLIST: RC0603_OV,RC0603,R603-X2,0603_CC; HEIGHT: 0.55 MM; MFG_NAME01: THYE MING TECH CO LTD; MFG_PN01: CR-03JL7----0R; ROHS: Yes; Tolerance: 5%
R5-R8 R105 R106 = RES: RES MF 10K 1/10W 5% 0603; AGILE_PN: 470-75410; CAD_APPROVED: Yes; FPLIST: RC0603_OV,RC0603,0603_CC; MFG_NAME01: KOA SPEER; MFG_PN01: RK73B1JTTD103J; ROHS: Yes; Tolerance: 5%
R17 R101 R102 = RES: RES MF 100K 1/10W 1% 0603; AGILE_PN: 470-75424; CAD_APPROVED: Yes; FPLIST: RC0603_OV,RC0603,0603_CC; MFG_NAME01: KOA SPEER; MFG_PN01: RK73H1JTTD1003F; ROHS: Yes; Tolerance: 1%
TP1-TP4 TP8-TP13 TP17-TP19 TP40-TP43 TP45-TP49 = Test_pad: TEST POINT PAD 35 MIL SMT, NO PART TO ORDER; AGILE_PN: 280-75148; ASSY_OPT: DNP; CAD_APPROVED: Yes; HEIGHT: 0.1 MM; MFG_NAME01: NA; MFG_PN01: NA; ROHS: Yes
TP5-TP7 TP44 = TestLoop: TEST POINT PAD 40MIL DIA SMT, NO PART TO ORDER; AGILE_PN: 211-76643; CAD_APPROVED: Yes; HEIGHT: 0.1MM; MFG_NAME01: NOTACOMPONENT; MFG_PN01: NOTACOMPONENT; ROHS: Yes
U1 = K60_LQ_LQFP_0: IC MCU 1MB FLASH 120MHZ 1.71-3.6V LQFP144; AGILE_PN: 344-01230; CAD_APPROVED: Yes; HEIGHT: 1.6MM; MFG_NAME01: FREESCALE SEMICONDUCTOR; ROHS: Yes
U2 = DS3231MZ: ASSY_OPT: DNP; CLASS: IC; MFG_NAME01: MAXIM; MFG_PN01: DS3231MZ+
Y1 = CLKGEN-SM: OSC 50MHZ FIXED 3.3V SMT; AGILE_PN: 230-77808; CAD_APPROVED: Yes; HEIGHT: 1.35MM; MFG_NAME01: PERICOM SEMICONDUCTOR; MFG_PN01: FD5000039; ROHS: Yes
R26 R81 = RES: RES MF 10.0K 1/10W 1% 0603; AGILE_PN: 470-75422; ASSY_OPT: DNP; CAD_APPROVED: Yes; FPLIST: RC0603_OV,RC0603,0603_CC; MFG_NAME01: KOA SPEER; MFG_PN01: RK73H1JTTD1002F; ROHS: Yes; Tolerance: 5%
U3 = 64LV25616AL: IC MEM SRAM 256KX16 12NS 3.3V TSOP44; AGILE_PN: 334-76618; CAD_APPROVED: Yes; HEIGHT: 1.2MM; MFG_NAME01: ISSI; ROHS: Yes
U4 = NC7SZ14: IC GATE NAND INV 3.3NS 1.65-5.5V SOT23_5P; AGILE_PN: 312-75975; CAD_APPROVED: Yes; HEIGHT: 1.45MM; MFG_NAME01: TEXAS INSTRUMENTS; MFG_PN01: SN74LVC1G04DBVT; ROHS: Yes
U5 = M25P32: IC MEM SERIAL FLASH 64MBIT 2.7-3.6V SO8W; AGILE_PN: 334-77338; CAD_APPROVED: Yes; HEIGHT: 2.5MM; MFG_NAME01: WINBOND ELECTRONICS CORP; ROHS: Yes
C34 C36 C39 C40 C42 C48 C50 C54 C55 = CAP_NP: CAP CER 3300PF 50V 5% C0G 0603; AGILE_PN: 150-77352; CAD_APPROVED: Yes; FPLIST: CC0603_OV,CC0603,0603_CC; HEIGHT: 0.9MM; MFG_NAME01: TDK; MFG_PN01: C1608C0G1H332J; ROHS: Yes; Tolerance: 5%; VOLTAGE: 50V
C35 C38 C43 C45-C47 C49 C53 = CAP_NP: CAP CER 0.01UF 50V 10% X5R 0603; AGILE_PN: 150-77071; CAD_APPROVED: Yes; FPLIST: CC0603_OV,CC0603,0603_CC; HEIGHT: 0.86MM; MFG_NAME01: AVX; MFG_PN01: 06035D103KAT2A; ROHS: Yes; Tolerance: 10%; VOLTAGE: 50V
C37 C52 = CAP_NP: CAP CER 1000PF 50V 10% C0G 0603; AGILE_PN: 150-75921; CAD_APPROVED: Yes; FPLIST: CC0603_OV,CC0603,0603_CC; HEIGHT: 0.91MM; MFG_NAME01: AVX; MFG_PN01: 06035U102KAT2A; ROHS: Yes; Tolerance: 10%; VOLTAGE: 50V
C41 C44 C51 = CAP_NP: CAP CER 4700pF 1000V 10% X7R 1210; AGILE_PN: 150-78925; CAD_APPROVED: Yes; FPLIST: CC1210,1210_CC; HEIGHT: 1.7MM; MFG_NAME01: AVX; MFG_PN01: 1210AC472KAT1A; ROHS: Yes; Tolerance: 10%; VOLTAGE: 1000V
CT1 CT2 = CT_2A
D3-D7 D13-D18 = DIODE_BIDIR_0: DIODE BIDIR ESD PROT 3.3V SOD323; AGILE_PN: 480-78083; CAD_APPROVED: Yes; HEIGHT: 1.1MM; MFG_NAME01: NXP SEMICONDUCTORS; MFG_PN01: PESD3V3L1BA,115; ROHS: Yes
J1 J2 J8 J9 = CONN_HDR_2X1: HDR 1X2 TH 100MIL SP 330H SN 120L; AGILE_PN: 210-79561; ASSY_OPT: DNP; CAD_APPROVED: Yes; HEIGHT: 8.39MM; MFG_NAME01: FRAMATOME CONNECTORS INTERNATIONAL; MFG_PN01: 69190-402HLF; ROHS: Yes
J3-J7 = CONN_HDR_2X1: HDR 1X2 TH 100MIL SP 330H SN 120L; AGILE_PN: 210-79561; CAD_APPROVED: Yes; HEIGHT: 8.39MM; MFG_NAME01: FRAMATOME CONNECTORS INTERNATIONAL; MFG_PN01: 69190-402HLF; ROHS: Yes
PT1-PT3 = PT_4P
R27 R29 R31 R34 R38 R46 R49 R54 R55 = RES: RES MF 100 OHM 1/10W 1% 0603; AGILE_PN: 470-75420; CAD_APPROVED: Yes; FPLIST: RC0603_OV,RC0603,0603_CC; MFG_NAME01: KOA SPEER; MFG_PN01: RK73H1JTTD1000F; ROHS: Yes; Tolerance: 1%
R28 R42 R44 R51 R53 = RES: RES MF 200 200V 0.1% 15PPM MELF0204; CAD_APPROVED: Yes; MFG_NAME01: WELWYN COMPONENTS LIMITED; MFG_PN01: WRM0204Y-200RBI; ROHS: Yes; Tolerance: 0.1%
R30 R32 = RES: RES MF 100 200V 0.1% 15PPM MELF0204; CAD_APPROVED: Yes; MFG_NAME01: WELWYN COMPONENTS LIMITED; MFG_PN01: WRM0204Y-390RBI; ROHS: Yes; Tolerance: 0.1%
R33 = RES: RES MF 200 200V 0.1% 15PPM MELF0204; CAD_APPROVED: Yes; MFG_NAME01: WELWYN COMPONENTS LIMITED; MFG_PN01: WRM0204Y-390RBI; ROHS: Yes; Tolerance: 0.1%
R35 R40 = RES: RES MF 11K 200V 0.1% 15PPM MELF0204; CAD_APPROVED: Yes; MFG_NAME01: WELWYN COMPONENTS LIMITED; MFG_PN01: WRM0204Y-390RBI; ROHS: Yes; Tolerance: 0.1%
R36 R41 R50 = RES: EE1/2 160K BC3 25PPM; MFG_NAME01: EBG; Tolerance: 0.1%
R37 R39 R162 R163 = RES: RES MF 10K 200V 0.1% 15PPM MELF0204; CAD_APPROVED: Yes; MFG_NAME01: WELWYN COMPONENTS LIMITED; MFG_PN01: WRM0204Y-390RBI; ROHS: Yes; Tolerance: 0.1%
R43 R52 = RES: RES MF 680 200V 0.1% 15PPM MELF0204; ASSY_OPT: DNP; CAD_APPROVED: Yes; MFG_NAME01: WELWYN COMPONENTS LIMITED; MFG_PN01: WRM0204Y-390RBI; ROHS: Yes; Tolerance: 0.1%
R45 = RES: RES MF 100K 200V 0.1% 15PPM MELF0204; CAD_APPROVED: Yes; MFG_NAME01: WELWYN COMPONENTS LIMITED; MFG_PN01: WRM0204Y-390RBI; ROHS: Yes; Tolerance: 0.1%
R47 = RES: RES MF 2K 200V 0.1% 15PPM MELF0204; CAD_APPROVED: Yes; MFG_NAME01: WELWYN COMPONENTS LIMITED; MFG_PN01: WRM0204Y-390RBI; ROHS: Yes; Tolerance: 0.1%
R48 = RES: RES MF ZERO OHM 1/2W -- 2010; CAD_APPROVED: Yes; MFG_NAME01: BOURNS; MFG_PN01: CR2010-J/-000ELF; ROHS: Yes; Tolerance: 0.1%
TVS1 = DIODE_TVS_BIDIR: DIODE TVS BIDIR 60V 600W DO-214AB; AGILE_PN: 480-78509; CAD_APPROVED: Yes; HEIGHT: 2.62MM; MFG_NAME01: LITTELFUSE; ROHS: Yes
U6 = OPAMP_QUAD_14P: IC LIN OPAMP QUAD 1.8-6V SOIC14; AGILE_PN: 315-79611; CAD_APPROVED: Yes; HEIGHT: 1.75 MM; MFG_NAME01: MICROCHIP TECHNOLOGY INC; ROHS: Yes
U7 = MAX44285: CLASS: IC; MFG_NAME01: MAXIM; ROHS: YES
U8 = ADR34XX_SOT23_6P: IC VOLTAGE REFERENCE 1.2V 2.3-5.5V SOT23-6; AGILE_PN: 315-80031; CAD_APPROVED: Yes; HEIGHT: 1.45MM; MFG_NAME01: ANALOG DEVICES; ROHS: Yes
U32 = OPAMP_DUAL_8P_D: IC LIN OPAMP DUAL 1MHZ 1.8-6V SOIC8; AGILE_PN: 315-79528; CAD_APPROVED: Yes; HEIGHT: 1.75MM; MFG_NAME01: MICROCHIP TECHNOLOGY INC; ROHS: Yes
V1-V3 = VARISTOR: VARISTOR 350V 10% 0.25W RADIAL; AGILE_PN: 470-80124; CAD_APPROVED: Yes; MFG_NAME01: Bourns; ROHS: Yes
C65 C66 C76 = CAP_NP: CAP CER 1000PF 2000V +80%/-20% X7R CC1206; AGILE_PN: 150-30088; CAD_APPROVED: Yes; FPLIST: CC1206_OV,CC1206,1206_CC; HEIGHT: 1.63mm; MFG_NAME01: NOVACAP; MFG_PN01: 1206B102Z202N; ROHS: Yes; VOLTAGE: 2000V
C77 C78 = CAP_NP: CAP CER 18PF 50V 5% C0G 0603; AGILE_PN: 150-75116; CAD_APPROVED: Yes; FPLIST: CC0603_OV,CC0603,0603_CC; HEIGHT: 0.90MM; MFG_NAME01: YAGEO AMERICA; MFG_PN01: CC0603JRNPO9BN180; ROHS: Yes; Tolerance: 5%; VOLTAGE: 50V
P1 P2 = RJ45_LED: CON 8 RJ-45 SHLD RA TH Y/G LEDS 40MIL SP 516H AU 105L; AGILE_PN: 210-79449; CAD_APPROVED: Yes; HEIGHT: 13.3MM; MFG_NAME01: PULSE ENGINEERING; MFG_PN01: E5J88-14LJD2-L; ROHS: Yes
R59-R62 R75-R78 = RES: RES MF 49.9 OHM 1/10W 1% 0603; AGILE_PN: 470-75432; CAD_APPROVED: Yes; FPLIST: RC0603_OV,RC0603,0603_CC; HEIGHT: 0.55 MM; MFG_NAME01: KOA SPEER; MFG_PN01: RK73H1JTTD49R9F; PRIORITY_PN: 006-00482; ROHS: Yes; ROOM: RMII_PHY; Tolerance: 1%
R65 R66 R92 R93 = RES: RES MF 75 OHM 1/10W 1% 0603; AGILE_PN: 470-75826; CAD_APPROVED: Yes; FPLIST: RC0603_OV,RC0603,0603_CC; HEIGHT: 0.55 MM; MFG_NAME01: KOA SPEER; MFG_PN01: RK73H1JTTD75R0F; ROHS: Yes; Tolerance: 1%
R67 R68 R94 R99 R100 = RES: RES MF 470 OHM 1/10W 1% 0603; AGILE_PN: 470-30133; CAD_APPROVED: Yes; FPLIST: RC0603_OV,RC0603,0603_CC; MFG_NAME01: KOA SPEER; MFG_PN01: RK73H1JTTD4700F; ROHS: Yes; Tolerance: 5%
R70 R107 R108 = RES: RES MF ZERO OHM 1/10W -- 0603; AGILE_PN: 470-75407; ASSY_OPT: DNP; CAD_APPROVED: Yes; FPLIST: RC0603_OV,RC0603,R603-X2,0603_CC; HEIGHT: 0.55 MM; MFG_NAME01: THYE MING TECH CO LTD; MFG_PN01: CR-03JL7----0R; ROHS: Yes; SIGNAL_MODEL: DEFAULT_RESISTOR_0.001OHM_2_1; Tolerance: 5%
R72 = RES: RES MF ZERO 1/8W 0805; AGILE_PN: 470-80547; CAD_APPROVED: Yes; FPLIST: RC0805_OV,RC0805,RC0805_OV_3P,0805_CC; MFG_NAME01: Vishay Intertechnology; MFG_PN01: CRCW08050000Z0EA; ROHS: Yes; Tolerance: 5%
R73 = RES: RES MF 12.1K  1/10W 1% 0603; AGILE_PN: 470-75516; CAD_APPROVED: Yes; FPLIST: RC0603_OV,RC0603,0603_CC; MFG_NAME01: KOA SPEER; MFG_PN01: RK73H1JTTD1212F; ROHS: Yes; Tolerance: 1%
R97 = RES: RES MF 6.80K 1/10W 1% 0603; AGILE_PN: 470-30137; CAD_APPROVED: Yes; HEIGHT: 0.55 MM; MFG_NAME01: KOA SPEER; MFG_PN01: RK73H1JTTD6801F; ROHS: Yes; Tolerance: 1%
T1 T2 = H1102: XFMR MAG-10/100BASE-T SINGLE PORT SMT; AGILE_PN: 560-30001; CAD_APPROVED: Yes; HEIGHT: 5.97 MM; MFG_NAME01: PULSE ENGINEERING; PART_TYPE: TRANSFORMERS; ROHS: Yes
U9 U10 U13 U14 = SRV05-4: DIODE TVS ARRAY 12A 5V 300W SOT23_S6; AGILE_PN: 480-75205; CAD_APPROVED: Yes; HEIGHT: 1.45mm; MFG_NAME01: SEMTECH CORP; MFG_PN01: SRV05-4.TCT; ROHS: Yes
U11 = LAN8720A-QFN24: IC XCVR ETHERNET 1.6-3.6V QFN24; AGILE_PN: 312-79651; CAD_APPROVED: Yes; HEIGHT: 1MM; MFG_NAME01: SMSC; MFG_PN01: LAN8720A-CP-TR; PRIORITY_PN: 051-LAN8720; ROHS: Yes; ROOM: RMII_PHY
U12 = DM9000A_QFP48: IC CTLR ETHERNET 10/100M 3.3V LQFP48; AGILE_PN: 312-80486; CAD_APPROVED: Yes; HEIGHT: 1.6 MM; MFG_NAME01: DAVICOM; MFG_PN01: DM9000AEP; ROHS: Yes
Y2 = CRYSTAL: XTAL 25MHZ 50PPM 8PF SMT; AGILE_PN: 230-75607; CAD_APPROVED: Yes; HEIGHT: 1.5MM; MFG_NAME01: NDK; MFG_PN01: NX5032GA-25.000000MHZ; ROHS: Yes
D8 D9 = LED: LED ULTRA BRIGHT RED SGL 30MA 0603; AGILE_PN: 370-75079; CAD_APPROVED: Yes; HEIGHT: 0.9MM; MFG_NAME01: LITE ON; MFG_PN01: LTST-C190KRKT; ROHS: Yes
J10 = HDR_2X10: MFG_NAME01: PINREX ENTERPRISE CO., LTD
Q1 Q2 = NPN: TRAN NPN GEN 200MA 40V SOT-23; AGILE_PN: 480-75173; CAD_APPROVED: Yes; HEIGHT: 1.12 MM; MFG_NAME01: ON SEMICONDUCTOR; ROHS: Yes
R103 R104 = RES: RES MF 10K 1/10W 5% 0603; AGILE_PN: 470-75410; ASSY_OPT: DNP; CAD_APPROVED: Yes; FPLIST: RC0603_OV,RC0603,0603_CC; MFG_NAME01: KOA SPEER; MFG_PN01: RK73B1JTTD103J; ROHS: Yes; Tolerance: 5%
SW1 SW2 = SW_PB_ESW: SW SPST MOM NO PB TACT 50mA 50V SMT; AGILE_PN: 510-77562; CAD_APPROVED: Yes; HEIGHT: 5MM; MFG_NAME01: E SWITCH; MFG_PN01: TL3301AF260QG/TR; ROHS: Yes
U15 U16 = PHOTOCOUPLER_4P: TRAN NPN PHOTOCOUPLER 80MA 80V DIP4; AGILE_PN: 480-78489; CAD_APPROVED: Yes; HEIGHT: 4.55MM; MFG_NAME01: CEL; ROHS: Yes

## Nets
AGND: R107.2 R108.2 ; also on sheet 8
GND: BT1.1(pos1) C1.2 C2.2 C3.2 C4.2 C5.2 C6.2 C7.2 C8.2 C9.2 C10.2 C17.2 C18.2 C19.2 C20.2 C21.2 C22.2 C23.2 C24.2 C25.2 C26.2 C27.2 C28.2 C29.2 C30.2 C31.2 C60.2 C61.2 C62.2 C63.2 C64.2 C66.1 C67.2 C68.2 C69.2 C70.2 C71.2 C72.2 C73.2 C74.2 C75.2 C77.2 C78.2 C125.2 C126.2 J10.2 L2.2 Q1.2(EMITTER) Q2.2(EMITTER) R26.1 R67.2 R72.1 R73.2 R74.1 R88.1 R94.2 R97.2 SW1.1(A1) SW1.2(A2) SW2.1(A1) SW2.2(A2) U1.6(VSS1) U1.17(VSS2) U1.18(VSSUSB) U1.44(VSS3) U1.57(VSS4) U1.71(VSS5) U1.93(VSS6) U1.107(VSS7) U1.121(VSS8) U1.134(VSS9) U2.5(GND) U3.12(GND1) U3.34(GND2) U4.3(GND) U5.4(VSS) U9.2(GND) U10.2(GND) U11.25(VSS) U12.5(RXGND1) U12.6(TXGND) U12.15(GND1) U12.33(GND2) U12.41(TEST) U12.45(GND3) U12.47(RXGND2) U12.48(BGGND) U13.2(GND) U14.2(GND) Y1.2(GND) ; also on sheet 7 8 9 10 11
GND_EARTH: C65.2 C66.2 C76.2 P1.S1 P1.S2 P2.S1 P2.S2 R72.2 ; also on sheet 7 9 11
GNDA: C11.2 C12.2 C13.2 C14.2 C15.2 C16.2 C32.2 C33.2 C34.2 C35.2 C36.2 C38.1 C39.2 C40.1 C42.2 C43.2 C45.1 C47.2 C48.2 C49.2 C50.2 C53.1 C54.1 C55.2 C56.2 C57.2 C58.2 C59.2 C117.2 C118.2 C119.2 C120.2 C121.2 C122.2 C124.2 D3.C(C2) D4.C(C2) D5.C(C2) D6.C(C2) D7.C(C2) D13.C(C2) D14.C(C2) D15.C(C2) D16.C(C2) D17.C(C2) D18.C(C2) J5.2 L2.1 R47.2 R163.2 TVS1.1(A1) U1.33(VREFL) U1.34(VSSA) U6.11(VEE) U7.5(GND) U8.1(GND_FORCE) U8.2(GND_SENSE) U32.4(VSS)
P3V3_LICELL: BT1.2(pos2) C27.1 D2.A R17.1
VBAT: C23.1 C24.1 C25.1 D1.C D2.C R17.2 U1.42(VBAT) U2.6(VBAT)
VCC_3V3: L4.2 ; also on sheet 11
VDD_3V3: C1.1 C2.1 C3.1 C4.1 C5.1 C6.1 C7.1 C8.1 C9.1 C10.1 C22.1 C26.1 C28.1 C29.1 C30.1 C31.1 C62.1 C69.1 C70.1 C71.1 D1.A D8.A(ANODE) D9.A(ANODE) J10.1 L3.2 L11.1 P2.10(LED2+) R1.1 R5.1 R6.1 R7.1 R8.1 R16.1 R23.2 R24.2 R25.2 R56.2 R57.2 R58.2 R71.1 R79.2 R80.2 R81.2 R82.2 R83.2 R109.1 R110.1 U1.5(VDD1) U1.16(VDD2) U1.43(VDD3) U1.56(VDD4) U1.70(VDD5) U1.94(VDD6) U1.108(VDD7) U1.122(VDD8) U1.135(VDD9) U2.2(VCC) U3.11(VDD1) U3.33(VDD2) U4.5(VCC) U5.8(VCC) U11.9(VDDIO) U12.23(VDD1) U12.30(VDD2) U12.42(VDD3) U15.1(ANODE) U16.1(ANODE) Y1.4(VDD) ; also on sheet 7 8 9 10 11
VDD_5V: C19.1 R3.2 ; also on sheet 7 8 10 11
VDDA_2V5: C72.1 C73.1 C74.1 C75.1 T2.2 T2.7 U12.2(RXVDD25) U12.9(TXVDD25) U13.5(VCC)
VDDA_3V3: C15.1 C16.1 C32.1 C33.1 C56.1 C57.1 C117.1 C118.1 L1.2 L3.1 L4.1 U1.31(VDDA) U6.4(VCC) U7.8(VDD) U8.3(ENABLE) U8.4(VIN) U32.8(VDD)
VDDCR_1.2V: C67.1 C68.1 U11.6(VDDCR)
ADC_S1: TP4.1(Pin1) U1.80(PTA29/ADC2_SE12/ULPI_DATA7/MII0_COL/FB_A24)
ADC_S2: TP3.1(Pin1) U1.79(PTA28/ADC2_SE13/ULPI_DATA6/MII0_TXER/FB_A25)
ADC_S3: TP2.1(Pin1) U1.78(PTA27/ADC2_SE14/ULPI_DATA5/MII0_CRS/FB_A26)
ADC_S4: TP1.1(Pin1) U1.77(PTA26/ADC2_SE15/ULPI_DATA4/MII0_TXD3/FB_A27)
DC_A1_OUT: U1.59(PTA7/ADC0_SE10/ULPI_DIR/FTM0_CH4/I2S1_RX_BCLK/TRACE_D3)
DC_A1_OUT (page PAGE04 ADC): C55.1 R55.2
DC_IN: J6.1 R48.1 U7.1(RS1+)
DC_OUT: J6.2 R48.2 U7.2(RS1-)
DC_V1_IN: C46.1 J5.1 R45.1 TVS1.2(A2)
DC_V1_OUT: U1.60(PTA8/ADC0_SE11/ULPI_NXT/FTM1_CH0/I2S1_RX_FS/FTM1_QD_PHA/TRACE_D2)
DC_V1_OUT (page PAGE04 ADC): C48.1 R46.2
DEBUG_RX: U1.51(PTA1/TSI0_CH2/UART0_RX/FTM0_CH6/JTAG_TDI/EZP_DI)
DEBUG_TX: U1.52(PTA2/TSI0_CH3/UART0_TX/FTM0_CH7/JTAG_TDO/TRACE_SWO/EZP_DO)
DM9000_INT#: U1.137(PTD8/I2C0_SCL/UART5_RX/FB_A16/NFC_CLE)
DM9000_INT# (page PAGE05 Ethernet): R95.2
DM9000_WAKE: U1.73(PTA19/XTAL/FTM1_FLT0/FTM_CLKIN1/LPTMR0_ALT1)
DM9000_WAKE (page PAGE05 Ethernet): R91.1
DM_INT: R83.1 R95.1 U12.34(INT)
DM_LED1: P2.9(LED2-) U12.39(LED1)
DM_LED2: P2.12(LED1+) U12.38(LED2)
EECLK: R80.1 U12.20(EECLK)
EECS: R79.1 U12.21(EECS)
ENET1_RX+: R59.2 T1.6 U9.3(I/O3) U11.23(RXP)
ENET1_RX-: R60.2 T1.8 U9.4(I/O4) U11.22(RXN)
ENET1_TX+: R61.2 T1.1 U9.1(I/O1) U11.21(TXP)
ENET1_TX-: R62.2 T1.3 U9.6(I/O6) U11.20(TXN)
ENET2_RX+: R77.2 T2.6 U12.3(RX+) U13.3(I/O3)
ENET2_RX-: R78.2 T2.8 U12.4(RX-) U13.4(I/O4)
ENET2_TX+: R75.2 T2.1 U12.7(TX+) U13.1(I/O1)
ENET2_TX-: R76.2 T2.3 U12.8(TX-) U13.6(I/O6)
ENET_3V3A: C60.1 C61.1 C63.1 C64.1 L11.2 P1.10(LED2+) R59.1 R60.1 R61.1 R62.1 R70.2 T1.2 T1.7 U9.5(VCC) U11.1(VDD2A) U11.19(VDD1A)
Eth1_RXN: P1.6 T1.9 U10.3(I/O3)
Eth1_RXP: P1.3 T1.11 U10.4(I/O4)
Eth1_TXN: P1.2 T1.14 U10.6(I/O6)
Eth1_TXP: P1.1 T1.16 U10.1(I/O1)
Eth2_RXN: P2.6 T2.9 U14.3(I/O3)
Eth2_RXP: P2.3 T2.11 U14.4(I/O4)
Eth2_TXN: P2.2 T2.14 U14.6(I/O6)
Eth2_TXP: P2.1 T2.16 U14.1(I/O1)
EXTAL: R18.2 U1.72(PTA18/EXTAL/FTM0_FLT2/FTM_CLKIN0)
EXTAL (page PAGE05 Ethernet): U11.5(XTAL1/CLKIN)
EZP_CS: R1.2 U1.54(PTA4/TSI0_CH5/FTM0_CH1/~{NMI}/~{EZP_CS})
FB_AD0: U1.133(PTD6/ADC0_SE7B/SPI0_PCS3/UART0_RX/FTM0_CH6/FB_AD0/FTM0_FLT0)
FB_AD0 (page PAGE03 Memory): U3.40(~{UB}) U4.2(A)
FB_AD0_N: U3.39(~{LB}) U4.4(Y)
FB_AD1: U1.132(PTD5/ADC0_SE6B/SPI0_PCS2/~{UART0_CTS}/~{UART0_COL}/FTM0_CH5/FB_AD1/NFC_DATA0/~{EWM_OUT})
FB_AD1 (page PAGE03 Memory): U3.1(A0)
FB_AD1 (page PAGE05 Ethernet): U12.32(CMD)
FB_AD2: U1.131(PTD4/SPI0_PCS1/~{UART0_RTS}/FTM0_CH4/FB_AD2/NFC_DATA1/EWM_IN)
FB_AD2 (page PAGE03 Memory): U3.2(A1)
FB_AD3: U1.130(PTD3/SPI0_SIN/UART2_TX/FTM3_CH3/FB_AD3/I2S1_RX_BCLK)
FB_AD3 (page PAGE03 Memory): U3.3(A2)
FB_AD4: U1.129(PTD2/SPI0_SOUT/UART2_RX/FTM3_CH2/FB_AD4/I2S1_RX_FS)
FB_AD4 (page PAGE03 Memory): U3.4(A3)
FB_AD5: U1.115(PTC10/ADC1_SE6B/I2C1_SCL/FTM3_CH6/FB_AD5/NFC_DATA2/I2S1_MCLK/I2S0_RX_FS)
FB_AD5 (page PAGE03 Memory): U3.5(A4)
FB_AD6: U1.114(PTC9/ADC1_SE5B/CMP0_IN3/FTM3_CH5/FB_AD6/NFC_DATA3/FTM2_FLT0/I2S0_RX_BCLK)
FB_AD6 (page PAGE03 Memory): U3.18(A5)
FB_AD7: U1.113(PTC8/ADC1_SE4B/CMP0_IN2/FTM3_CH4/FB_AD7/NFC_DATA4/I2S0_MCLK)
FB_AD7 (page PAGE03 Memory): U3.19(A6)
FB_AD8: U1.112(PTC7/CMP0_IN1/SPI0_SIN/USB_SOF_OUT/FB_AD8/NFC_DATA5/I2S0_RX_FS)
FB_AD8 (page PAGE03 Memory): U3.20(A7)
FB_AD9: U1.111(PTC6/CMP0_IN0/SPI0_SOUT/PDB0_EXTRG/FB_AD9/NFC_DATA6/I2S0_MCLK/I2S0_RX_BCLK)
FB_AD9 (page PAGE03 Memory): U3.21(A8)
FB_AD10: U1.110(PTC5/SPI0_SCK/LPTMR0_ALT2/FB_AD10/NFC_DATA7/CMP0_OUT/I2S1_TX_FS/I2S0_RXD0)
FB_AD10 (page PAGE03 Memory): U3.22(A9)
FB_AD11: U1.109(PTC4/SPI0_PCS0/UART1_TX/FTM0_CH3/FB_AD11/NFC_DATA8/I2S1_TX_BCLK/CMP1_OUT)
FB_AD11 (page PAGE03 Memory): U3.23(A10)
FB_AD12: U1.105(PTC2/ADC0_SE4B/TSI0_CH15/SPI0_PCS2/~{UART1_CTS}/FTM0_CH1/FB_AD12/NFC_DATA9/I2S0_TX_FS/CMP1_IN0)
FB_AD12 (page PAGE03 Memory): U3.24(A11)
FB_AD13: U1.104(PTC1/ADC0_SE15/TSI0_CH14/SPI0_PCS3/~{UART1_RTS}/FTM0_CH0/FB_AD13/NFC_DATA10/I2S0_TXD0)
FB_AD13 (page PAGE03 Memory): U3.25(A12)
FB_AD14: U1.103(PTC0/ADC0_SE14/TSI0_CH13/SPI0_PCS4/PDB0_EXTRG/FB_AD14/NFC_DATA11/I2S0_TXD1)
FB_AD14 (page PAGE03 Memory): U3.26(A13)
FB_AD15: U1.97(PTB18/TSI0_CH11/CAN0_TX/FTM2_CH0/FB_AD15/FTM2_QD_PHA/I2S0_TX_BCLK)
FB_AD15 (page PAGE03 Memory): U3.27(A14)
FB_AD16: U1.96(PTB17/TSI0_CH10/SPI1_SIN/UART0_TX/I2S1_TXD1/FB_AD16/~{EWM_OUT})
FB_AD16 (page PAGE03 Memory): U3.42(A15)
FB_AD17: U1.95(PTB16/TSI0_CH9/SPI1_SOUT/UART0_RX/I2S1_TXD0/FB_AD17/EWM_IN)
FB_AD17 (page PAGE03 Memory): U3.43(A16)
FB_AD18: U1.92(PTB11/ADC1_SE15/SPI1_SCK/UART3_TX/I2S1_TX_FS/FB_AD18/FTM0_FLT2)
FB_AD18 (page PAGE03 Memory): U3.44(A17)
FB_AD24: U1.120(PTC15/UART4_TX/FB_AD24)
FB_AD24 (page PAGE03 Memory): U3.7(I/O0) U3.29(I/O8)
FB_AD24 (page PAGE05 Ethernet): U12.18(SD0)
FB_AD25: U1.119(PTC14/UART4_RX/FB_AD25)
FB_AD25 (page PAGE03 Memory): U3.8(I/O1) U3.30(I/O9)
FB_AD25 (page PAGE05 Ethernet): U12.17(SD1)
FB_AD26: U1.118(PTC13/~{UART4_CTS}/FB_AD26)
FB_AD26 (page PAGE03 Memory): U3.9(I/O2) U3.31(I/O10)
FB_AD26 (page PAGE05 Ethernet): U12.16(SD2)
FB_AD27: U1.117(PTC12/~{UART4_RTS}/FB_AD27/FTM3_FLT0)
FB_AD27 (page PAGE03 Memory): U3.10(I/O3) U3.32(I/O11)
FB_AD27 (page PAGE05 Ethernet): U12.14(SD3)
FB_AD28: U1.102(PTB23/SPI2_SIN/SPI0_PCS5/FB_AD28/NFC_DATA12/CMP3_OUT)
FB_AD28 (page PAGE03 Memory): U3.13(I/O4) U3.35(I/O12)
FB_AD28 (page PAGE05 Ethernet): U12.13(SD4)
FB_AD29: U1.101(PTB22/SPI2_SOUT/FB_AD29/NFC_DATA13/CMP2_OUT)
FB_AD29 (page PAGE03 Memory): U3.14(I/O5) U3.36(I/O13)
FB_AD29 (page PAGE05 Ethernet): U12.12(SD5)
FB_AD30: U1.100(PTB21/ADC2_SE5A/SPI2_SCK/FB_AD30/NFC_DATA14/CMP1_OUT)
FB_AD30 (page PAGE03 Memory): U3.15(I/O6) U3.37(I/O14)
FB_AD30 (page PAGE05 Ethernet): U12.11(SD6)
FB_AD31: U1.99(PTB20/ADC2_SE4A/SPI2_PCS0/FB_AD31/NFC_DATA15/CMP0_OUT)
FB_AD31 (page PAGE03 Memory): U3.16(I/O7) U3.38(I/O15)
FB_AD31 (page PAGE05 Ethernet): U12.10(SD7)
FB_CS0_N: U1.128(PTD1/ADC0_SE5B/SPI0_SCK/~{UART2_CTS}/FTM3_CH1/~{FB_CS0}/I2S1_RXD0)
FB_CS0_N (page PAGE03 Memory): U3.6(~{CE})
FB_CS1_N: U1.127(PTD0/SPI0_PCS0/~{UART2_RTS}/FTM3_CH0/FB_ALE/~{FB_CS1}/~{FB_TS}/I2S1_RXD1)
FB_CS1_N (page PAGE05 Ethernet): U12.37(~{CS})
FB_OE_N: U1.98(PTB19/TSI0_CH12/CAN0_RX/FTM2_CH1/~{FB_OE}/FTM2_QD_PHB/I2S0_TX_FS)
FB_OE_N (page PAGE03 Memory): U3.41(~{OE})
FB_OE_N (page PAGE05 Ethernet): U12.35(~{IOR})
FB_RW_N: U1.116(PTC11/ADC1_SE7B/I2C1_SDA/FTM3_CH7/~{FB_RW}/NFC_WE/I2S0_RXD1)
FB_RW_N (page PAGE03 Memory): U3.17(~{WE})
FB_RW_N (page PAGE05 Ethernet): U12.36(~{IOW})
GP6: R82.1 TP13.1(Pin1) U12.25(SD13/GP6)
GPIO_1: U1.87(PTB6/ADC1_SE12/FB_AD23)
GPIO_1 (page PAGE06 GPIO): J10.3
GPIO_2: U1.88(PTB7/ADC1_SE13/FB_AD22)
GPIO_2 (page PAGE06 GPIO): J10.4
GPIO_3: U1.76(PTA25/CMP3_IN5/ULPI_DATA3/MII0_TXCLK/FB_A28)
GPIO_3 (page PAGE06 GPIO): J10.5
GPIO_4: U1.47(PTE26/ADC3_SE5B/ENET_1588_CLKIN/~{UART4_CTS}/I2S1_TXD0/RTC_CLKOUT/USB_CLKIN)
GPIO_4 (page PAGE06 GPIO): J10.6
GPIO_5: U1.48(PTE27/ADC3_SE4B/~{UART4_RTS}/I2S1_MCLK)
GPIO_5 (page PAGE06 GPIO): J10.7
GPIO_6: U1.49(PTE28/ADC3_SE7A)
GPIO_6 (page PAGE06 GPIO): J10.8
GPIO_7: U1.58(PTA6/ADC3_SE6A/ULPI_CLK/FTM0_CH3/I2S1_RXD0/TRACE_CLKOUT)
GPIO_7 (page PAGE06 GPIO): J10.9
GPIO_8: U1.61(PTA9/ADC3_SE5A/ULPI_STP/FTM1_CH1/MII0_RXD3/FTM1_QD_PHB/TRACE_D1)
GPIO_8 (page PAGE06 GPIO): J10.10
GPIO_9: U1.62(PTA10/ADC3_SE4A/ULPI_DATA0/FTM2_CH0/MII0_RXD2/FTM2_QD_PHA/TRACE_D0)
GPIO_9 (page PAGE06 GPIO): J10.11
GPIO_10: U1.63(PTA11/ADC3_SE15/ULPI_DATA1/FTM2_CH1/MII0_RXCLK/FTM2_QD_PHB)
GPIO_10 (page PAGE06 GPIO): J10.12
GPIO_IN_1: U1.85(PTB4/ADC1_SE10/ENET0_1588_TMR2/FTM1_FLT0)
GPIO_IN_1 (page PAGE06 GPIO): R109.2 SW1.3(B1) SW1.4(B2)
GPIO_IN_2: U1.86(PTB5/ADC1_SE11/ENET0_1588_TMR3/FTM2_FLT0)
GPIO_IN_2 (page PAGE06 GPIO): R110.2 SW2.3(B1) SW2.4(B2)
GPIO_OUT_1: U1.89(PTB8/~{UART3_RTS}/FB_AD21)
GPIO_OUT_1 (page PAGE06 GPIO): R101.2
GPIO_OUT_2: U1.90(PTB9/SPI1_PCS1/~{UART3_CTS}/FB_AD20)
GPIO_OUT_2 (page PAGE06 GPIO): R102.2
GPIO_OUT_3: U1.91(PTB10/ADC1_SE14/SPI1_PCS0/UART3_RX/I2S1_TX_BCLK/FB_AD19/FTM0_FLT1)
GPIO_OUT_3 (page PAGE06 GPIO): R106.2
GPIO_OUT_4: U1.138(PTD9/I2C0_SDA/UART5_TX/FB_A17/NFC_ALE)
GPIO_OUT_4 (page PAGE06 GPIO): R105.2
GPRS_CTS: U1.126(PTC19/~{UART3_CTS}/ENET0_1588_TMR3/~{FB_CS3}/~{FB_BE7_0_BLS31_24}/~{FB_TA})
GPRS_DCD: U1.141(PTD12/SPI2_SCK/FTM3_FLT0/SDHC0_D4/FB_A20)
GPRS_DTR: U1.140(PTD11/SPI2_PCS0/~{UART5_CTS}/SDHC0_CLKIN/FB_A19)
GPRS_PWR_CNTL: U1.144(PTD15/SPI2_PCS1/SDHC0_D7/FB_A23)
GPRS_RI: U1.142(PTD13/SPI2_SOUT/SDHC0_D5/FB_A21)
GPRS_RST: U1.143(PTD14/SPI2_SIN/SDHC0_D6/FB_A22)
GPRS_RTS: U1.125(PTC18/~{UART3_RTS}/ENET0_1588_TMR2/~{FB_TBST}/~{FB_CS2}/~{FB_BE15_8_BLS23_16}/~{NFC_CE1})
GPRS_RX: U1.124(PTC17/CAN1_TX/UART3_TX/ENET0_1588_TMR1/~{FB_CS4}/FB_TSIZ0/~{FB_BE31_24_BLS7_0}/~{NFC_CE0})
GPRS_TX: U1.123(PTC16/CAN1_RX/UART3_RX/ENET0_1588_TMR0/~{FB_CS5}/FB_TSIZ1/~{FB_BE23_16_BLS15_8}/NFC_RB)
I1A_IN: CT1.1 R28.1 U6.2(VINA-)
I1A_OUT: U1.25(ADC3_DP0/ADC2_DP3/ADC1_DP1)
I1A_OUT (page PAGE04 ADC): C34.1 R27.2
I2A_N: U1.24(ADC2_DM0/ADC3_DM3/ADC0_DM1)
I2A_N (page PAGE04 ADC): C37.2 C40.2 R34.2
I2A_P: U1.23(ADC2_DP0/ADC3_DP3/ADC0_DP1)
I2A_P (page PAGE04 ADC): C36.1 C37.1 R29.2
I2C_SCL: R6.2 R14.2 TP6.1(Pin1) U1.83(PTB2/ADC0_SE12/TSI0_CH7/I2C0_SCL/~{UART0_RTS}/ENET0_1588_TMR0/FTM0_FLT3)
I2C_SDA: R5.2 R15.2 TP5.1(Pin1) U1.84(PTB3/ADC0_SE13/TSI0_CH8/I2C0_SDA/~{UART0_CTS}/~{UART0_COL}/ENET0_1588_TMR1/FTM0_FLT0)
L_XIN: R96.2 U12.44(X1)
L_XOUT: C78.1 U12.43(X2) Y2.2
LED3: R90.2 U12.24(SD14/LED3)
MODE0: R56.1 R63.2 U11.8(RXD0/MODE0)
MODE1: R57.1 R64.2 U11.7(RXD1/MODE1)
norflash_wp: R23.1 R26.2 U5.3(~{W}/VPP)
PHY_INT_B: R71.2 U11.14(I~{NT}/REFCLKO)
PHY_LED1: P1.12(LED1+) U11.3(LED1/REGOFF)
PHY_LED2: R68.2 U11.2(LED2/I~{NTSEL})
PHY_RST_B: R69.2 U11.15(~{RST})
PWRST#: R98.2 U12.40(~{PWRST})
RBIAS: R73.1 U11.24(RBIAS)
RESET_B: R11.2 ; also on sheet 9
RESET_B (page PAGE05 Ethernet): R69.1 R98.1
RMII0_CRS_DV: U1.66(PTA14/CMP3_IN0/SPI0_PCS0/UART0_TX/RMII0_CRS_DV/MII0_RXDV/I2S0_RX_BCLK/I2S0_TXD1)
RMII0_CRS_DV (page PAGE05 Ethernet): R58.1 U11.11(CRS_DV/MODE2)
RMII0_MDC: R7.2 U1.82(PTB1/ADC0/1/2/3_SE9/TSI0_CH6/I2C0_SDA/FTM1_CH1/RMII0_MDC/MII0_MDC/FTM1_QD_PHB)
RMII0_MDC (page PAGE05 Ethernet): U11.13(MDC)
RMII0_MDIO: R8.2 U1.81(PTB0/ADC0/1/2/3_SE8/TSI0_WU/I2C0_SCL/FTM1_CH0/RMII0_MDIO/MII0_MDIO/FTM1_QD_PHA)
RMII0_MDIO (page PAGE05 Ethernet): U11.12(MDIO)
RMII0_RXD0: U1.65(PTA13/CAN0_RX/FTM1_CH1/RMII0_RXD0/MII0_RXD0/FTM1_QD_PHB/CMP2_IN1/I2S0_TX_FS)
RMII0_RXD0 (page PAGE05 Ethernet): R63.1
RMII0_RXD1: U1.64(PTA12/CAN0_TX/FTM1_CH0/RMII0_RXD1/MII0_RXD1/FTM1_QD_PHA/CMP2_IN0/I2S0_TXD0)
RMII0_RXD1 (page PAGE05 Ethernet): R64.1
RMII0_RXER: U1.55(PTA5/USB_CLKIN/FTM0_CH2/RMII0_RXER/MII0_RXER/~{JTAG_TRST}/CMP2_OUT/I2S0_TX_BCLK)
RMII0_RXER (page PAGE05 Ethernet): R70.1 R74.2 U11.10(RXER/PHYAD0)
RMII0_TXD0: R2.1
RMII0_TXD0 (page PAGE05 Ethernet): U11.17(TXD0)
RMII0_TXD1: R4.1
RMII0_TXD1 (page PAGE05 Ethernet): U11.18(TXD1)
RMII0_TXEN: U1.67(PTA15/CMP3_IN1/SPI0_SCK/UART0_RX/RMII0_TXEN/MII0_TXEN/I2S0_RXD0)
RMII0_TXEN (page PAGE05 Ethernet): U11.16(TXEN)
RS485_5V: R103.1 R104.1 ; also on sheet 8
RS485I_DIR: U1.14(PTE11/ADC3_SE16/~{UART5_RTS}/FTM3_CH6/I2S0_TX_FS)
RS485I_RX: U1.46(PTE25/ADC0_SE18/XTAL1/CAN1_RX/UART4_RX/I2S1_TX_BCLK/EWM_IN/I2S1_TXD1)
RS485I_TX: U1.45(PTE24/ADC0_SE17/EXTAL1/CAN1_TX/UART4_TX/I2S1_TX_FS/~{EWM_OUT}/I2S1_RXD1)
RS485II_DIR: U1.13(PTE10/~{UART5_CTS}/FTM3_CH5/I2S0_TXD0)
RS485II_RX: U1.12(PTE9/ADC2_SE17/UART5_RX/FTM3_CH4/I2S0_TXD1/I2S0_RX_BCLK)
RS485II_TX: U1.11(PTE8/ADC2_SE16/UART5_TX/FTM3_CH3/I2S0_RXD1/I2S0_RX_FS)
RTC_XTALI: C21.1 QZ1.2 R12.2
RTC_XTALO: C20.1 QZ1.1 U1.40(XTAL32)
SPI1_PCS0: U1.7(PTE4/SPI1_PCS0/UART3_TX/SDHC0_D3)
SPI1_PCS0 (page PAGE03 Memory): R24.1 U5.1(~{S})
SPI1_PCS2: U1.8(PTE5/SPI1_PCS2/UART3_RX/SDHC0_D2/FTM3_CH0)
SPI1_SCK: R13.1
SPI1_SCK (page PAGE03 Memory): U5.6(C)
SPI1_SIN: U1.4(PTE3/ADC1_SE7A/SPI1_SIN/~{UART1_RTS}/SDHC0_CMD/SPI1_SOUT)
SPI1_SIN (page PAGE03 Memory): U5.2(Q)
SPI1_SOUT: U1.2(PTE1/ADC1_SE5A/SPI1_SOUT/UART1_RX/SDHC0_D0/I2C1_SCL/SPI1_SIN)
SPI1_SOUT (page PAGE03 Memory): U5.5(D)
SWD_CLK: U1.50(PTA0/TSI0_CH1/~{UART0_CTS}/~{UART0_COL}/FTM0_CH5/JTAG_TCLK/SWD_CLK/EZP_CLK)
SWD_DIO: U1.53(PTA3/TSI0_CH4/~{UART0_RTS}/FTM0_CH0/JTAG_TMS/SWD_DIO)
U1_L: C41.1 J3.2 R36.1 V1.1
U1_N: C41.2 J3.1 PT1.2 V1.2
U1P_IN: PT1.4 R33.1 U6.6(VINB-)
U1P_OUT: U1.36(ADC0_SE16/ADC0_SE21/CMP1_IN2)
U1P_OUT (page PAGE04 ADC): C39.1 R31.2
U2_IN_L: C43.1 D15.A(C1) PT2.4 R37.1 R42.1 R43.1
U2_IN_N: C45.2 D16.A(C1) PT2.3 R39.1 R43.2 R44.2
U2_L: C44.1 J4.2 R41.1 V2.1
U2_N: C44.2 J4.1 PT2.2 V2.2
U2P_OUT: U1.27(ADC0_DP0/ADC1_DP3)
U2P_OUT (page PAGE04 ADC): C42.1 R38.2
U3_IN_N: U1.30(ADC1_DM0/ADC0_DM3)
U3_IN_N (page PAGE04 ADC): C52.2 C54.2 R54.2
U3_IN_P: U1.29(ADC1_DP0/ADC0_DP3)
U3_IN_P (page PAGE04 ADC): C50.1 C52.1 R49.2
U3_L: C51.1 J7.2 R50.1 V3.1
U3_N: C51.2 J7.1 PT3.2 V3.2
UART1_RX: U1.106(PTC3/SPI0_PCS1/UART1_RX/FTM0_CH2/FB_CLKOUT/I2S0_TX_BCLK/CMP1_IN1)
UART1_TX: U1.1(PTE0/ADC1_SE4A/SPI1_PCS1/UART1_TX/SDHC0_D1/I2C1_SDA/RTC_CLKOUT)
USB_5V: R3.1 U1.22(VREGIN)
USB_Host_D_N: R10.2 ; also on sheet 7
USB_Host_D_P: R9.2 ; also on sheet 7
VOUT33: C17.1 C18.1 U1.21(VOUT33)
VREF_1V2: C58.1 C59.1 L10.1 TP7.1(Pin1) U8.5(VOUT_SENSE) U8.6(VOUT_FORCE)
VREF_ADC: C123.1 L9.2 L10.2 L26.2 L27.2 R162.1
VREF_ADC_HALF: C119.1 C120.1 C121.1 C122.1 CT1.2 L26.1 PT1.3 R30.2 R32.1 R35.1 R51.2 R53.1 TP44.1(Pin1) U6.3(VINA+) U6.5(VINB+) U32.1(1OUT) U32.2(1IN-) U32.6(2IN-) U32.7(2OUT)
VREF_HALF: C123.2 C124.1 R162.2 R163.1 U32.3(1IN+) U32.5(2IN+)
VREF_OUT: C11.1 C12.1 L9.1 U1.37(VREF_OUT/CMP0_IN5/ADC1_SE18/CMP1_IN5)
VREFH: C13.1 C14.1 L1.1 L27.1 U1.32(VREFH)
WAKE: R81.1 R88.2 R91.2 U12.22(SD15/WAKE)
WDOG: U1.75(PTA24/CMP3_IN4/ULPI_DATA2/MII0_TXD2/FB_A29)
WIFI/LCD_GPIO1: U1.9(PTE6/SPI1_PCS3/~{UART3_CTS}/FTM3_CH1/USB_SOF_OUT/I2S0_MCLK)
WIFI/LCD_GPIO2: U1.10(PTE7/~{UART3_RTS}/FTM3_CH2/I2S0_RXD0)
WIFI/LCD_GPIO3: U1.15(PTE12/ADC3_SE17/FTM3_CH7/I2S0_TX_BCLK)
WIFI/LCD_GPIO4: U1.139(PTD10/~{UART5_RTS}/FB_A18/NFC_RE)
WIFI/LCD_PWR_CNTL: U1.136(PTD7/CMT_IRO/UART0_TX/FTM0_CH7/FTM0_FLT1)
N16756265: R65.1 T1.10
N16756269: R66.1 T1.15
N16759319: R25.1 U5.7(~{HOLD})
N16772440: D3.A(C1) R27.1 R28.2 U6.1(VOUTA)
N16775214: D4.A(C1) R31.1 R33.2 U6.7(VOUTB)
N16775930: D5.A(C1) R38.1 R40.2 U6.8(VOUTC)
N16775968: R35.2 R37.2 U6.10(VINC+)
N16775998: R39.2 R40.1 U6.9(VINC-)
N16783367: C46.2 C47.1 R45.2 R47.1 U6.12(VIND+)
N16785222: C53.2 D17.A(C1) L8.1 PT3.3 R52.2 R53.2
N16785246: PT3.1 R50.2
N16785292: C49.1 D18.A(C1) L7.1 PT3.4 R51.1 R52.1
N16786136: L8.2 R54.1
N16786139: L7.2 R49.1
N16788483: D6.A(C1) R46.1 U6.13(VIND-) U6.14(VOUTD)
N16806806: C77.1 R96.1 Y2.1
N16812858: R2.2 U1.68(PTA16/CMP3_IN2/SPI0_SOUT/~{UART0_CTS}/~{UART0_COL}/RMII0_TXD0/MII0_TXD0/I2S0_RX_FS/I2S0_RXD1)
N16812861: R4.2 U1.69(PTA17/ADC1_SE17/SPI0_SIN/~{UART0_RTS}/RMII0_TXD1/MII0_TXD1/I2S0_MCLK)
N16858143: P1.11(LED1-) R67.1
N16858278: P1.9(LED2-) R68.1
N16861702: R92.1 T2.10
N16861704: R93.1 T2.15
N16899253: R97.1 U12.1(BGRES)
N16906260: P2.11(LED1-) R94.1
N16913941: R84.2 U12.31(SD8/GP1)
N16913953: R85.2 U12.29(SD9/GP2)
N16913968: R86.2 U12.28(SD10/GP3)
N16913982: R87.2 U12.27(SD11/GP4)
N16913996: R89.2 U12.26(SD12/GP5)
N16917794: R11.1 U1.74(~{RESET})
N16918817: R12.1 U1.41(EXTAL32)
N16919212: R16.2 Y1.1(OE)
N16919504: R18.1 Y1.3(CLKOUT)
N16920348: R9.1 U1.19(USB0_DP)
N16920352: R10.1 U1.20(USB0_DM)
N16922932: D8.C(CATHODE) R99.1
N16922934: Q1.3(COLLECTOR) R99.2
N16922936: Q1.1(BASE) R101.1
N16922944: Q2.3(COLLECTOR) R100.2
N16922946: D9.C(CATHODE) R100.1
N16922998: R106.1 U15.2(CATHODE)
N16923008: J8.2 R104.2 U15.4(COLLECTOR)
N16923020: J8.1 R108.1 U15.3(EMITTER)
N16923032: R105.1 U16.2(CATHODE)
N16923042: J9.2 R103.2 U16.4(COLLECTOR)
N16923054: J9.1 R107.1 U16.3(EMITTER)
N16932299: PT2.1 R41.2
N16932357: R42.2 R44.1
N16935752: C38.2 CT2.2 D14.A(C1) L6.1 R32.2
N16935822: C35.1 CT2.1 D13.A(C1) L5.1 R30.1
N16935990: L6.2 R34.1
N16935992: L5.2 R29.1
N16963015: R89.1 TP12.1(Pin1)
N16963035: R84.1 TP9.1(Pin1)
N16963490: R85.1 TP10.1(Pin1)
N16963499: R86.1 TP8.1(Pin1)
N16963508: R87.1 TP11.1(Pin1)
N16992640: R13.2 U1.3(PTE2/ADC1_SE6A/SPI1_SCK/~{UART1_CTS}/SDHC0_DCLK)
N17002202: J10.15 TP18.1(Pin1)
N17002209: J10.14 TP17.1(Pin1)
N17002232: J10.16 TP19.1(Pin1)
N17009409: D7.A(C1) R55.1 U7.7(OUT1)
N17038152: R14.1 U2.8(SCL)
N17038155: R15.1 U2.7(SDA)
N17045351: J10.17 TP40.1(Pin1)
N17045355: J10.19 TP41.1(Pin1)
N17045369: J10.18 TP42.1(Pin1)
N17045378: J10.20 TP43.1(Pin1)
N17061950: Q2.1(BASE) R102.1
N17108951: C65.1 R65.2 R66.2
N17109053: C76.1 R92.2 R93.2
N17159947: PT1.1 R36.2
N17166355: C125.1 R75.1 R76.1
N17166431: C126.1 R77.1 R78.1
N17167419: J10.13 TP45.1(Pin1)
N17171737: TP46.1(Pin1) U1.38(DAC0_OUT/ADC0_SE23/CMP1_IN3)
N17171740: TP47.1(Pin1) U1.39(DAC1_OUT/ADC1_SE23/CMP2_IN3)
N17171751: TP48.1(Pin1) U1.35(ADC1_SE16/ADC0_SE22/CMP2_IN2)
N17171755: TP49.1(Pin1) U1.26(ADC3_DM0/ADC2_DM3/ADC1_DM1)

Not connected (* = marked no-connect by the designer): J1 1* 2*; J2 1* 2*; P1 4* 5* 7* 8*; P2 4* 5* 7* 8*; R90 1*; T1 4(NC4)* 5(NC5)* 12(NC12)* 13(NC13)*; T2 4(NC4)* 5(NC5)* 12(NC12)* 13(NC13)*; U1 28(ADC0_DM0/ADC1_DM3)*; U2 1(32KHz)* 3(~{INT}/SQW)* 4(~{RST})*; U3 28(NC)*; U4 1(NC)*; U7 3(RS2+)* 4(RS2-)* 6(OUT2)*; U10 5(VCC)*; U11 4(XTAL2)*; U12 19(EEDIO)* 46(SD)*; U14 5(VCC)*

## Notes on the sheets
sheet 1
- Revision History
- Rev
- Date
- Description
- A
- 04/23/2014
- CS0
- 512kB SRAM
- FLEX
   BUS
- CS1
- DM9000
- RJ45
- PT
- AC Voltage
- ADCx3
- PHY
- RJ45
- MAC
- CT
- AC Current
- ADCx2
- SPI1
- SPI Nor Flash
- Amplifier
- DC Voltage
- ADC
- K64
- WIFI/LCD Connector
- Current
   Sensor
- DC Current
- ADC
- GPRS Module
- UART
- MAX13485
- RS485
- UART
  x2
- USB
  Full Speed
- USB
- Debug
    DB9
- UART
  x2
- MAX3232
- WatchDog
- GPIO
- GPIO
  x16
- GPIO IN/OUT
- 5V
- LDO@3.3V
- Reference
     Power
- DC5V IN
- @1.2V
- DCDC@3.3V
- ISOLATED
     Power
- @5V
- External@5V
sheet 2
- UART0_RX
- UART0_TX
- 喂狗信号
- VREFH  Default:
- Internal 1.2V
- GPIO信号
- I2C信号
- Flexbus信号
- 丝印：
  I2C_SDA; I2C_SCL
- Debug信号
- UART1_RX
- ADC信号
- RS485信号
- 差分
  直接接K64 ADC
- UART3_RX
- UART3_TX
- UART3_RTS
- UART3_CTS
- RS485_DIR:
- 高为发送，低为接收
- RMII信号
- GPRS信号
- UART1_TX
- SPI信号
- UART5_TX
- UART5_RX
- UART4_TX
- UART4_RX
- 其他
- 模拟3.3V 来源可选
- RTC Coin Cell
sheet 3
- 256K*16bit SRAM
- Flexbus信号
- 8bit
- 写 低电平有效
- 8MB SPI NOR
sheet 4
- 电流量程0~6A，CT变比1000:1
- Signle End
- RC低通滤波，截止频率：
- f=500kHZ
- AC 电流
- AC电流量程0~6A，CT变比5A:2.5mA
- ADC电压计算公式：
- 由于电压互感器负载要求小于200ohm，产生的电压差1V左右,如果不经过运放，做不到满量程
- IxA_OUT= VREF_ADC+I*R1
- R1
- 1/4W
- 差分
  直接接K64 ADC
- AC 电流
- MAX44252高精度低噪声
- AC电压量程AC 0~400V，PT变比2.5mA:2.5mA
- ADC电压计算公式：
- R1
- UxP_OUT= VREF_ADC+I*R1
- 1/4W
- Rf
- R1
- 单端经运放放大，单端输出
- AC 电压
- R1
- AC电压量程AC 0~400V，PT变比2.5mA:2.5mA
- ADC电压计算公式：
- Rf
- Vout=(Vl-Vn)*Rf/R1+Vref_adc
- 差分经运放放大，单端输出
- AC 电压
- DC 电压监测
- Vout=Vl*R1/(R1+R2)
- R2
- 最大电压
- DC 电压
- 0~60V
- 400V
- V_L-N=1000mV
- R1
- 由于电压互感器负载要求小于400ohm，产生的电压差1V左右,如果不经过运放，做不到满量程
- Rsens
- DC 电流
- 0~60V
- AC 电压
- 差分
  直接接K64 ADC
- 0~100mA
- DC 电流监测
- 从电阻两端走差分线到芯片
- Vout=I*Rsens*Gain
- Gain=20V/V
- 最大电压
- V_L-N<1.2V
- 400V
- VREF_ADC_REF: 0.6V
- V_L-N=1000mV
- Current Sensor
- 分压电路
- Output: 1.2V 0.1% @+10/-3mA
- ADC参考电源 来源可选
- 兼容MAX6071
- 跟随，增强驱动能力
- MCU VREFH选择为1.2V， L26 DNP
- MCU VREFH选择为3.3V， L26焊接，U32 DNP
sheet 5
- 两级保护
- Mode Bus
- 111:  All Capable
- RMII信号
- Link/Active
- Speed
- Internal 1.2V reg enabled
- Link/Active
- nINT ON
- Speed
- PHY ADDR:0x0 (default)
- DM9000A信号
- Strap Setting
- 1:  8-bit
- 1:  INT low active
- 1:  INT open drain
- 0:  CS Low Active
- Link/Active
- Speed
- LED3
- WAKEUP
- INT
- CMD
- Speed
- Link/Active
- 两级保护
- Place crystal close to Chip
sheet 6
- GPIO信号
